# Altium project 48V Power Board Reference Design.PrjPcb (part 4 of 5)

## Sheet Power.SchDoc
size 431 x 279 mm; Date: Not shown in title block; ApprovedBy: Not shown in title block; CheckedBy: Not shown in title block; Author: Not shown in title block; CompanyName: Not shown in title block; Engineer: Not shown in title block; Organization: Not shown in title block; Address1: Not shown in title block; Address2: Not shown in title block; Address3: Not shown in title block; Address4: Not shown in title block; DocumentNumber: 5; Revision: Use project parameter SCH_Rev; SheetNumber: 14; SheetTotal: 15; PageSetup: Record=PageOptions¦CenterHorizontal=True¦CenterVertical=True¦PrintScale=1.00¦XCorrection=1.00¦YCorrection=1.00¦PrintKind=0¦BorderSize=5000000¦LeftOffset=0¦BottomOffset=0¦Orientation=2¦PaperLength=1000¦PaperWidth=1000¦Scale=100¦PaperSource=15¦PrintQuality=600¦MediaType=1¦DitherType=10¦PaperKind=Letter¦PrintScaleMode=1
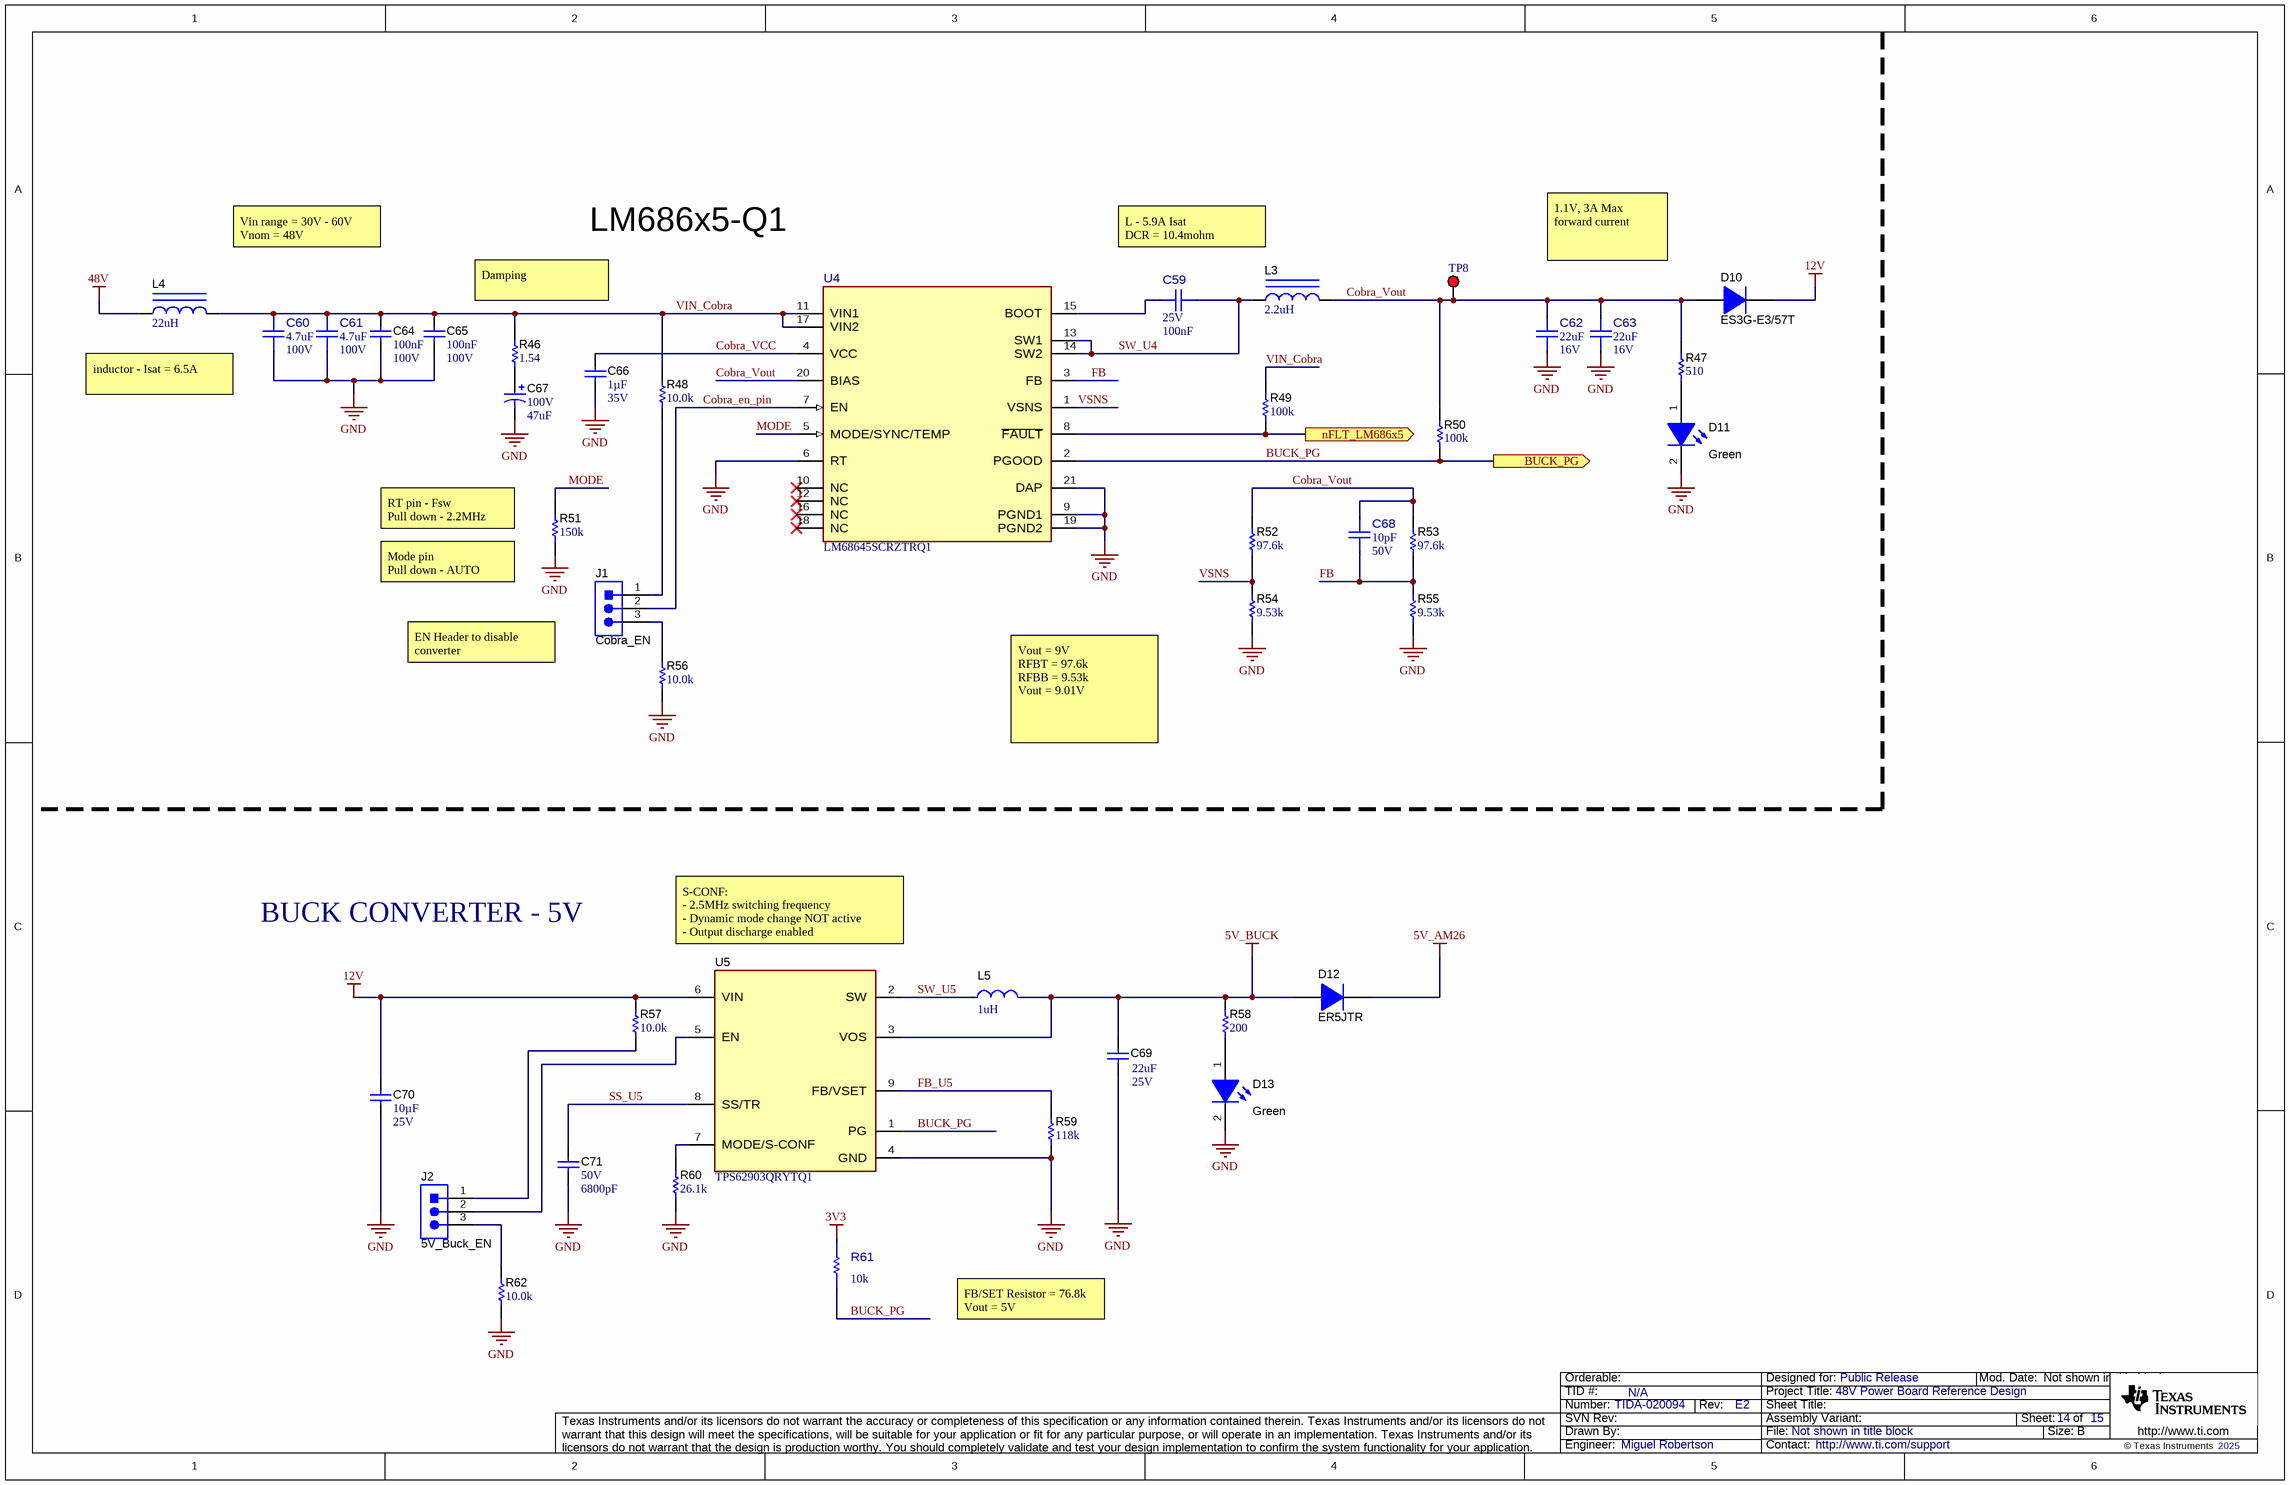
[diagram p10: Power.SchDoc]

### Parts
C59  VDC_V: 25V  Cap_F: 100nF  [FP-GCJ188R71E104KA12D_0603-MFG]  (hidden comment: GCJ188R71E104KA12D)
C60  ValueDisplayed: 4.7uF  VDC_V: 100V  [FP-GCJ32DC72A475KE01L_1210-MFG]  (hidden comment: GCJ32DC72A475KE01L)
C61  ValueDisplayed: 4.7uF  VDC_V: 100V  [FP-GCJ32DC72A475KE01L_1210-MFG]  (hidden comment: GCJ32DC72A475KE01L)
C62  ValueDisplayed: 22uF  VDC_V: 16V  [FP-EMK316BB7226ML-T_1206-MFG]  (hidden comment: EMK316BB7226ML-T)
C63  ValueDisplayed: 22uF  VDC_V: 16V  [FP-EMK316BB7226ML-T_1206-MFG]  (hidden comment: EMK316BB7226ML-T)
C64  Cap_F: 100nF  VDC_V: 100V  [0603]  (hidden comment: HMK107B7104KAHT)
C65  Cap_F: 100nF  VDC_V: 100V  [0603]  (hidden comment: HMK107B7104KAHT)
C66  Cap_F: 1µF  VDC_V: 35V  [0603]  (hidden comment: CGA3E1X7R1V105K080AE)
C67  VDC_V: 100V  ValueDisplayed: 47uF  [SM_RADIAL_H13]  (hidden comment: EEV-FK2A470Q)
C68  ValueDisplayed: 10pF  VDC_V: 50V  [FP-C0402C100K5RAC7867_0402-MFG]  (hidden comment: C0402C100K5RAC7867)
C69  VDC_V: 25V  ValueDisplayed: 22uF  [0805_HV]  (hidden comment: GRM21BR61E226ME44L)
C70  Cap_F: 10µF  VDC_V: 25V  [0805_HV]  (hidden comment: GRM21BZ71E106KE15L)
C71  VDC_V: 50V  ValueDisplayed: 6800pF  [0402]  (hidden comment: GRM155R71H682KA88D)
D10  ES3G-E3/57T  [SMC]
D11  value Green  [LTST-C191_Green]  (hidden comment: LTST-C191KGKT)
D12  ER5JTR  [SMC]
D13  value Green  [LTST-C191_Green]  (hidden comment: LTST-C191KGKT)
J1  Cobra_EN  [TSW-103-07-G-S]
J2  5V_Buck_EN  [TSW-103-07-G-S]
L3  ValueDisplayed: 2.2uH  [WE-TPC-XLH2]  (hidden comment: 7440650022)
L4  ValueDisplayed: 22uH  [WE-PD_1210]  (hidden comment: 7447709220)
L5  value 1uH  [FP-XGL4030-102MEC_SMD_IND_4MM0_4MM0-MFG]  (hidden comment: XGL4030-102MEC)
R46  ValueDisplayed: 1.54  [0603]  (hidden comment: CRCW06031R54FKEA)
R47  ValueDisplayed: 510  [0603]  (hidden comment: RC0603FR-07510RL)
R48  ValueDisplayed: 10.0k  [0603]  (hidden comment: ERJ-3EKF1002V)
R49  ValueDisplayed: 100k  [0603]  (hidden comment: RT0603BRD07100KL)
R50  ValueDisplayed: 100k  [0603]  (hidden comment: RT0603BRD07100KL)
R51  ValueDisplayed: 150k  [0603]  (hidden comment: ERJ-3EKF1002V)
R52  ValueDisplayed: 97.6k  [0603]  (hidden comment: RC0603FR-0797K6L)
R53  ValueDisplayed: 97.6k  [0603]  (hidden comment: RC0603FR-0797K6L)
R54  ValueDisplayed: 9.53k  [0603]  (hidden comment: RC0603FR-079K53L)
R55  ValueDisplayed: 9.53k  [0603]  (hidden comment: RC0603FR-079K53L)
R56  ValueDisplayed: 10.0k  [0603]  (hidden comment: ERJ-3EKF1002V)
R57  ValueDisplayed: 10.0k  [0603]  (hidden comment: ERJ-3EKF1002V)
R58  ValueDisplayed: 200  [0603]  (hidden comment: RC0603FR-07200RL)
R59  ValueDisplayed: 118k  [0603]  (hidden comment: CRCW0603118KFKEA)
R60  ValueDisplayed: 26.1k  [0603]  (hidden comment: RC0603FR-0726K1L)
R61  value 10k  [FP-RC0402JR-0710KL_0402-MFG]  (hidden comment: RC0402JR-0710KL)
R62  ValueDisplayed: 10.0k  [0603]  (hidden comment: ERJ-3EKF1002V)
TP8  COBRA_VOUT  [Keystone5010]  (value not drawn)
U4  LM68645SCRZTRQ1  [RZT0020A-MFG]
U5  TPS62903QRYTQ1  [RYT0009A-MFG]

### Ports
BUCK_PG (out), nFLT_LM686x5 (out)

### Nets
3V3: R61.2
5V_AM26: D12.1(K)
5V_BUCK: C69.1 D12.2(A) L5.2 R58.2 U5.3(VOS)
12V: C70.1 D10.1(K) R57.2 U5.6(VIN)
48V: L4.1
GND: C60.1 C61.1 C62.1 C63.1 C64.2 C65.2 C66.2 C67.2(-) C69.2 C70.2 C71.2 D11.2(K) D13.2(K) R51.1 R54.1 R55.1 R56.1 R59.1 R60.1 R62.1 U4.6(RT) U4.9(PGND1) U4.19(PGND2) U4.21(DAP) U5.4(GND)
BUCK_PG: R50.1 R61.1 U4.2(PGOOD) U5.1(PG) ; port BUCK_PG
Cobra_en_pin: J1.2 U4.7(EN)  [project net Cobra_en_pin_14]
Cobra_VCC: C66.1 U4.4(VCC)  [project net Cobra_VCC_14]
Cobra_Vout: C62.2 C63.2 C68.2 D10.2(A) L3.2 R47.2 R50.2 R52.2 R53.2 TP8.1 U4.20(BIAS)  [project net Cobra_Vout_14]
FB: C68.1 R53.1 R55.2 U4.3(FB)  [project net FB_14]
FB_U5: R59.2 U5.9(FB/VSET)  [project net FB_U5_14]
MODE: R51.2 U4.5(MODE/SYNC/TEMP)  [project net MODE_14]
nFLT_LM686x5: R49.1 U4.8(~{FAULT}) ; port nFLT_LM686x5
SS_U5: C71.1 U5.8(SS/TR)  [project net SS_U5_14]
SW_U4: C59.1 L3.1 U4.13(SW1) U4.14(SW2)  [project net SW_U4_14]
SW_U5: L5.1 U5.2(SW)  [project net SW_U5_14]
VIN_Cobra: C60.2 C61.2 C64.1 C65.1 L4.2 R46.2 R48.2 R49.2 U4.11(VIN1) U4.17(VIN2)  [project net VIN_Cobra_14]
VSNS: R52.1 R54.2 U4.1(VSNS)  [project net VSNS_14]
NetC59_2: C59.2 U4.15(BOOT)
NetC67_1: C67.1(+) R46.1
NetD11_1: D11.1(A) R47.1
NetD13_1: D13.1(A) R58.1
NetJ1_1: J1.1 R48.1
NetJ1_3: J1.3 R56.2
NetJ2_1: J2.1 R57.1
NetJ2_2: J2.2 U5.5(EN)
NetJ2_3: J2.3 R62.2
NetR60_2: R60.2 U5.7(MODE/S-CONF)

Not connected (* = marked no-connect by the designer): U4 10(NC)* 12(NC)* 16(NC)* 18(NC)*

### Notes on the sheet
- LM686x5-Q1
- Vin range = 30V - 60V                        Vnom = 48V
- Damping
- L - 5.9A Isat
  DCR = 10.4mohm
- 1.1V, 3A Max forward current
- inductor - Isat = 6.5A
- (near R51) RT pin - Fsw                          Pull down - 2.2MHz
- (near R51) Mode pin                           Pull down - AUTO
- EN Header to disable converter
- Vout = 9V
  RFBT = 97.6k
  RFBB = 9.53k
  Vout = 9.01V
- BUCK CONVERTER - 5V
- S-CONF:
  - 2.5MHz switching frequency
  - Dynamic mode change NOT active
  - Output discharge enabled
- FB/SET Resistor = 76.8k
  Vout = 5V

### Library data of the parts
C59 = CMP-0095670-2: Cap Ceramic 0.1uF 25V X7R 10% Pad SMD 0603 Soft Termination +125°C Automotive T/R; Manufacturer: Murata; Value: 100nF; AEC Qualified: Yes; AEC Grade: Grade 1; SizeZ_mm: 0.9mm; TempCo: 15%
C60 C61 = CMP-0093675-1: 4.7uF ±10% 100V Ceramic Capacitor X7S 1210 (3225 Metric); Manufacturer: Murata; Value: 4.7µF; AEC Qualified: Yes; TempCo: 22%; SizeZ_mm: 2.3mm; AEC Grade: Grade 1
C62 C63 = CMP-0123888-1: Ceramic Capacitor, 1206, 22uF, 20%, X7R, 15%, 16V; Manufacturer: Taiyo Yuden; AEC Qualified: No; Cap_F: 22µF; SizeZ_mm: 1.9mm; Value: 22µF
C64 C65 = CMP-0081011-1: CAP, CERM, 0.1 µF, 100 V,+/- 10%, X7R, AEC-Q200 Grade 1, 0603; Manufacturer: Taiyo Yuden; SizeAreaWB_mm2: 4.68; SizeArea_mm2: 1.28; AEC Qualified: Y; AEC Category: Q200; Value: 0.1uF; TaMax_C: 125°C; SizeZ_mm: 1; Polarized: N; TaMin_C: -55°C; SizeY_mm: 0.8; U/M: EA; SizeX_mm: 1.6; ValueDisplayed: 0.1µF
C66 = CMP-0081259-1: CAP, CERM, 1 µF, 35 V,+/- 10%, X7R, AEC-Q200 Grade 1, 0603; Manufacturer: TDK; SizeAreaWB_mm2: 4.68; SizeArea_mm2: 1.28; AEC Qualified: Y; AEC Category: Q200; Value: 1uF; TaMax_C: 125°C; SizeZ_mm: 1; Polarized: N; TaMin_C: -55°C; SizeY_mm: 0.8; U/M: EA; SizeX_mm: 1.6
C67 = CMP-0011225-2: CAP, AL, 47 uF, 100 V, +/- 20%, 0.32 ohm, AEC-Q200 Grade 2, SMD; Manufacturer: Panasonic; TaMin_C: -55°C; ESR_ohm: 0.32; Polarized: Y; SizeAreaWB_mm2: 263.5; U/M: EA; Value: 47uF; TaMax_C: 105°C; SizeZ_mm: 13.5; SizeX_mm: 15; Cap_Case: H13; SizeArea_mm2: 202.5; CompType: Capacitor; Cap_F: 47µF; IRMS_A: 500mA; AEC Grade: 2; AEC Category: Q200
C68 = CMP-0122034-1: 10 pF ±10% 50V Ceramic Capacitor X7R 0402 (1005 Metric); Manufacturer: KEMET; AEC Qualified: No; SizeZ_mm: 0.55mm; TempCo: 15%; Value: 10pF
C69 = CMP-0008305-2: CAP, CERM, 22 uF, 25 V, +/- 20%, X5R, 0805; Manufacturer: MuRata; TaMin_C: -55°C; Polarized: N; SizeAreaWB_mm2: 6.75; Value1: Unknown; U/M: EA; Value: 22uF; TaMax_C: 85°C; SizeZ_mm: 1.45; SizeX_mm: 2; SizeY_mm: 1.25; Cap_Case: 0805; SizeArea_mm2: 2.5; Cap_F: 22µF; AEC Category: Q200
C70 = CMP-0008378-2: CAP, CERM, 10 uF, 25 V, +/- 10%, X7R, 0805; Manufacturer: MuRata; TaMin_C: -55°C; Polarized: N; SizeAreaWB_mm2: 6.75; Value1: Unknown; U/M: EA; Value: 10uF; TaMax_C: 125°C; SizeZ_mm: 1.45; SizeX_mm: 2; SizeY_mm: 1.25; Cap_Case: 0805; SizeArea_mm2: 2.5; AEC Category: Q200
C71 = CMP-0006696-2: CAP, CERM, 6800 pF, 50 V, +/- 10%, X7R, 0402; Manufacturer: MuRata; TaMin_C: -55°C; Polarized: N; SizeAreaWB_mm2: 3; Value1: Unknown; U/M: EA; Value: 6800pF; TaMax_C: 125°C; SizeZ_mm: 0.6; SizeX_mm: 1; SizeY_mm: 0.5; Cap_F: 6.8nF; AEC Category: Q200
D10 = CMP-0077028-2: Diode, Ultrafast, 400 V, 3 A, SMC; Manufacturer: Vishay-Semiconductor; Green_Lifecycle: Not Set; SizeAreaWB_mm2: 83.2686; Vr_V: 400V; SizeY_mm: 6.22; Value1: 3A; TJmax_C: 150°C; SizeZ_mm: 2.6; Green_REACh: Incomplete; Vf_V: 1.1V; SizeArea_mm2: 50.5686; SizeX_mm: 8.13; Value: 400V; AEC Category: Q101
D11 D13 = CMP-0078478-1: LED, Green, SMD; Manufacturer: Lite-On; Io_A: 30mA; Power_TotalModule: 75mW; Green_Lifecycle: Not Set; Vr_V: 5V; Tjmax_C: 85°C; Green_REACh: Incomplete; Value1: 0.075W; Angle: 130; Ir_A: 10µA; Vf_V: 2V; Type: AlInGaP
D12 = CMP-0067546-2: Diode, Superfast Rectifier, 600 V, 5 A, SMC; Manufacturer: SMC Diode Solutions; Vr_V: 600V; TJmax_C: 150°C; Io_A: 5A; Value: 600V; SizeX_mm: 8.13; AEC Category: Q101; Vf_V: 1.7V; SizeY_mm: 6.22; SizeAreaWB_mm2: 83.2686; RJC_CperW: 47.0; SizeZ_mm: 2.6; SizeArea_mm2: 50.5686; AEC Qualified: N
J1 J2 = CMP-0075407-2: Header, 100mil, 3x1, Gold, TH; Manufacturer: Samtec; Pitch_mm: 2.54; Cert_VDE: N; Gender: Male; Cert_CSA: Y; Voltage_V: 550V; Green_REACh: Passed; Current_A: 6.3A; Green_Lifecycle: Active; Row_Count: 1
L3 = CMP-0063847-1: Inductor, Shielded Drum Core, Ferrite, 2.2 uH, 5.9 A, 0.0104 ohm, SMD; Manufacturer: Wurth Elektronik; Isat: 5.9A @ 35% inductance drop; Irms: 6.2A @ 30C rise; Green_Lifecycle: Active; SizeAreaWB_mm2: 144; DCR_ohm: 10.4m; Green_REACh: Passed; Value: 2.2uH; Imax_A: 5.9A; SizeZ_mm: 2.8; SizeX_mm: 10; SizeArea_mm2: 100; Ind_H: 2.2µH; AEC Category: Q200
L4 = CMP-0064538-2: Inductor, Shielded Drum Core, Ferrite, 22 uH, 5.3 A, 0.0233 ohm, SMD; Manufacturer: Wurth Elektronik; Isat: 6.5A @ 10% inductance drop; Irms: 5.3A @ 40C rise; Green_Lifecycle: Active; SizeAreaWB_mm2: 196; DCR_ohm: 23.3m; Green_REACh: Passed; Value: 22uH; Imax_A: 5.3A; SizeZ_mm: 10; SizeX_mm: 12; SizeArea_mm2: 144; Ind_H: 22µH; AEC Category: Q200
L5 = CMP-0090842-1: Power Inductor, shielded, composite, 1uH 20% tol, DCR 7.2mOhms, SRF 65MHz, Isat 4.8A, Irms 13A, AEC-Q200; Manufacturer: Coilcraft; TaMin_C: -40°C; TaMax_C: +125°C; Test Frequency: 1MHz; DCR_ohm: 7.2m; AEC Grade: Grade 1; SizeZ_mm: 3.1mm; AEC Qualified: Yes; Shrouded: true; Ind_H: 1µH
R46 = CMP-0022188-4: RES, 1.54, 1%, 0.1 W, AEC-Q200 Grade 0, 0603; Manufacturer: Vishay-Dale; Power_W: 100mW; TempCo: 100 ppm/C; Value_Code: 1R54; Value: 1.54; EIA_Code: E96; SizeX_mm: 1.6; SizeY_mm: 0.8; SizeZ_mm: 1; Value2: 0.1W; SizeArea_mm2: 1.28; AEC Qualified: Y; VDC_V: 75V; AEC Category: Q200; AEC Grade: 0
R47 = CMP-0023163-5: RES, 510, 1%, 0.1 W, 0603; Manufacturer: Yageo; Power_W: 100mW; TempCo: 100 ppm/C; Value_Code: 510R; Value: 510; SizeX_mm: 1.6; SizeY_mm: 0.8; SizeZ_mm: 1; Value2: 0.1W; SizeArea_mm2: 1.28; AEC Qualified: N; VDC_V: 75V; AEC Category: Q200; SizeAreaWB_mm2: 4.68
R48 R51 R56 R57 R62 = CMP-0022684-3: RES, 10.0 k, 1%, 0.1 W, 0603; Manufacturer: Panasonic; Power_W: 100mW; TempCo: 100 ppm/C; Value_Code: 10k0; U/M: EA; Value: 10.0k; EIA_Code: E96; Res_ohm: 10k; SizeX_mm: 1.6; SizeY_mm: 0.8; SizeZ_mm: 1; Value2: 0.1W; SizeArea_mm2: 1.28; VDC_V: 75V; AEC Category: Q200
R49 R50 = CMP-0023630-1: RES, 100 k, 0.1%, 0.1 W, 0603; Manufacturer: Yageo America; Power_W: 100mW; TempCo: 25 ppm/C; U/M: EA; Value: 100k; EIA_Code: E192; SizeX_mm: 1.6; SizeY_mm: 0.8; SizeZ_mm: 1; Value2: 0.1W; SizeArea_mm2: 1.28; VDC_V: 75V; AEC Category: Q200
R52 R53 = CMP-0023330-5: RES, 97.6 k, 1%, 0.1 W, 0603; Manufacturer: Yageo; Power_W: 100mW; TempCo: 100 ppm/C; Value_Code: 97k6; Value: 97.6k; EIA_Code: E96; SizeX_mm: 1.6; SizeY_mm: 0.8; SizeZ_mm: 1; Value2: 0.1W; SizeArea_mm2: 1.28; AEC Qualified: N; VDC_V: 75V; AEC Category: Q200; SizeAreaWB_mm2: 4.68
R54 R55 = CMP-0023335-5: RES, 9.53 k, 1%, 0.1 W, 0603; Manufacturer: Yageo; Power_W: 100mW; TempCo: 100 ppm/C; Value_Code: 9k53; Value: 9.53k; EIA_Code: E96; SizeX_mm: 1.6; SizeY_mm: 0.8; SizeZ_mm: 1; Value2: 0.1W; SizeArea_mm2: 1.28; AEC Qualified: N; VDC_V: 75V; AEC Category: Q200; SizeAreaWB_mm2: 4.68
R58 = CMP-0022902-5: RES, 200, 1%, 0.1 W, 0603; Manufacturer: Yageo; Power_W: 100mW; TempCo: 100 ppm/C; Value_Code: 200R; Value: 200; EIA_Code: E96; SizeX_mm: 1.6; SizeY_mm: 0.8; SizeZ_mm: 1; Value2: 0.1W; SizeArea_mm2: 1.28; AEC Qualified: N; VDC_V: 75V; AEC Category: Q200; SizeAreaWB_mm2: 4.68
R59 = CMP-0022014-4: RES, 118 k, 1%, 0.1 W, AEC-Q200 Grade 0, 0603; Manufacturer: Vishay-Dale; Power_W: 100mW; TempCo: 100 ppm/C; Value: 118k; EIA_Code: E96; SizeX_mm: 1.6; SizeY_mm: 0.8; SizeZ_mm: 1; Value2: 0.1W; SizeArea_mm2: 1.28; AEC Qualified: Y; VDC_V: 75V; AEC Category: Q200; AEC Grade: 0
R60 = CMP-0022957-5: RES, 26.1 k, 1%, 0.1 W, 0603; Manufacturer: Yageo; Power_W: 100mW; TempCo: 100 ppm/C; Value_Code: 26k1; Value: 26.1k; EIA_Code: E96; SizeX_mm: 1.6; SizeY_mm: 0.8; SizeZ_mm: 1; Value2: 0.1W; SizeArea_mm2: 1.28; AEC Qualified: N; VDC_V: 75V; AEC Category: Q200; SizeAreaWB_mm2: 4.68
R61 = CMP-0094798-1: Res Thick Film 0402 10K Ohm 5% 0.063W(1/16W) ±100ppm/C Pad SMD T/R; Manufacturer: YAGEO; Power_W: 63mW; TempCo: 100ppm/°C; SizeZ_mm: 0.4mm; AEC Qualified: No; VDC_V: 50V; Category Cd01000Bfc2916C6: Single Components; Category 5C6A91606D4187Ad: Resistors; Category 7542B8484461Ae85: Passive Components
TP8 = CMP-0055147-2: Test Point, Multipurpose, Red, TH; Manufacturer: Keystone Electronics; CT: TRUE; ContactFinish: Silver; Green_Lifecycle: Active; CNHeader: FALSE; Green_REACh: Passed
U4 = CMP-0096221-1: 3.5V to 65V Synchronous Step-Down Voltage Regulator; Manufacturer: Texas Instruments; Switching Topology: Buck; Number Of Outputs: 1; AEC Qualified: Yes; Standoff Height: 0mm; Output Type: AdjustableProgrammable; SizeZ_mm: 0.7mm
U5 = CMP-0093448-1: 3-V to 18-V, High Efficiency and Low IQ Buck Converter in QFN HR  Package with 165C Junction temperature; Manufacturer: Texas Instruments; SizeZ_mm: 1.05mm; Min Supply Voltage: 3V; Output Type: AdjustableProgrammable; Switching Frequency: 1/2.5MHz; Max Supply Voltage: 18V; Output Voltage: 0.4-5.5V; Number Of Outputs: 1; TJmax_C: +165°C; Standoff Height: 0mm; Nominal Supply Current: 8mA; AEC Qualified: Yes; AEC Grade: Grade 1; Max Duty Cycle: 100%

## Sheet (SPI Expander) TXE8124-Q1.SchDoc
size 431 x 279 mm; Date: Not shown in title block; ApprovedBy: Not shown in title block; CheckedBy: Not shown in title block; Author: Not shown in title block; CompanyName: Not shown in title block; Engineer: Not shown in title block; Organization: Not shown in title block; Address1: Not shown in title block; Address2: Not shown in title block; Address3: Not shown in title block; Address4: Not shown in title block; DocumentNumber: 1; Revision: Use project parameter SCH_Rev; SheetNumber: 13; SheetTotal: 15; PageSetup: Record=PageOptions¦CenterHorizontal=True¦CenterVertical=True¦PrintScale=1.00¦XCorrection=1.00¦YCorrection=1.00¦PrintKind=0¦BorderSize=5000000¦LeftOffset=0¦BottomOffset=0¦Orientation=2¦PaperLength=1000¦PaperWidth=1000¦Scale=100¦PaperSource=15¦PrintQuality=600¦MediaType=1¦DitherType=10¦PaperKind=Letter¦PrintScaleMode=1
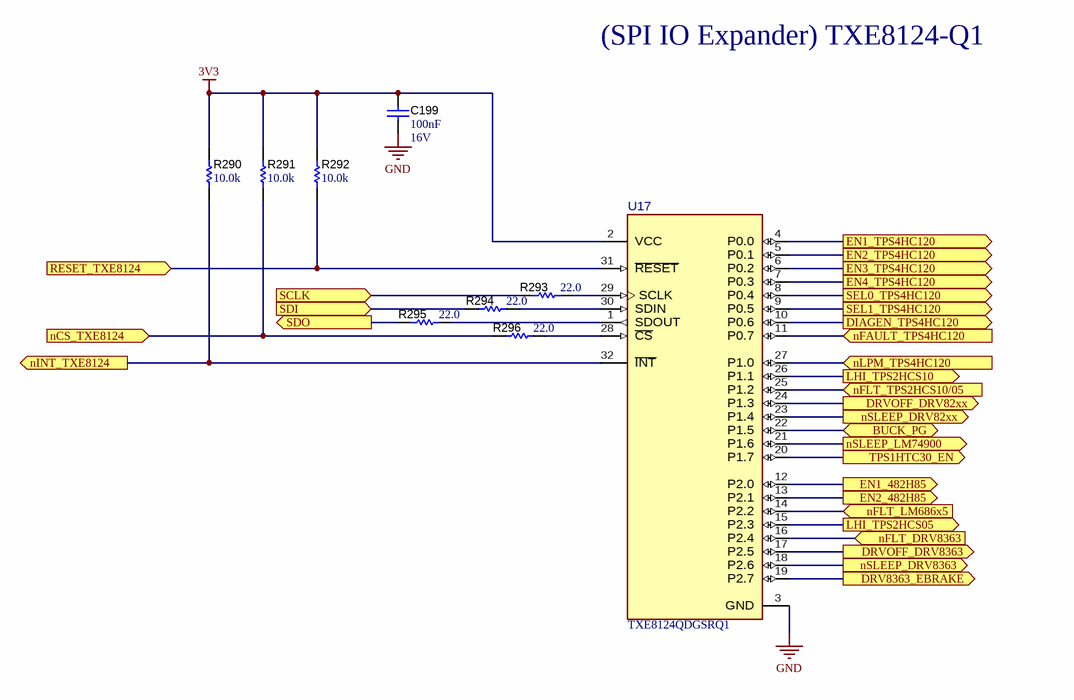
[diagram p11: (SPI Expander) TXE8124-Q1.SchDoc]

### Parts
C199  Cap_F: 100nF  VDC_V: 16V  [0603]  (hidden comment: GCM188R71C104KA37J)
R290  ValueDisplayed: 10.0k  [0603]  (hidden comment: ERJ-3EKF1002V)
R291  ValueDisplayed: 10.0k  [0603]  (hidden comment: ERJ-3EKF1002V)
R292  ValueDisplayed: 10.0k  [0603]  (hidden comment: ERJ-3EKF1002V)
R293  ValueDisplayed: 22.0  [0201]  (hidden comment: RC0201FR-0722RL)
R294  ValueDisplayed: 22.0  [0201]  (hidden comment: RC0201FR-0722RL)
R295  ValueDisplayed: 22.0  [0201]  (hidden comment: RC0201FR-0722RL)
R296  ValueDisplayed: 22.0  [0201]  (hidden comment: RC0201FR-0722RL)
U17  TXE8124QDGSRQ1  [DGS0032A-MFG]

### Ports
BUCK_PG (bidir), DIAGEN_TPS4HC120 (out), DRV8363_EBRAKE (out), DRVOFF_DRV82xx (out), DRVOFF_DRV8363 (out), EN1_482H85 (out), EN1_TPS4HC120 (out), EN2_482H85 (out), EN2_TPS4HC120 (out), EN3_TPS4HC120 (out), EN4_TPS4HC120 (out), LHI_TPS2HCS05 (out), LHI_TPS2HCS10 (out), nCS_TXE8124 (in), nFAULT_TPS4HC120 (in), nFLT_DRV8363 (in), nFLT_LM686x5 (in), nFLT_TPS2HCS10/05 (in), nINT_TXE8124 (out), nLPM_TPS4HC120 (in), nSLEEP_DRV82xx (out), nSLEEP_DRV8363 (out), nSLEEP_LM74900 (out), RESET_TXE8124 (in), SCLK (in), SDI (in), SDO (out), SEL0_TPS4HC120 (out), SEL1_TPS4HC120 (out), TPS1HTC30_EN (out)

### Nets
3V3: C199.1 R290.1 R291.1 R292.1 U17.2(VCC)
GND: C199.2 U17.3(GND)
: R294.1 ; port SDI
BUCK_PG: U17.22(P1.5) ; port BUCK_PG
DIAGEN_TPS4HC120: U17.10(P0.6) ; port DIAGEN_TPS4HC120
DRV8363_EBRAKE: U17.19(P2.7) ; port DRV8363_EBRAKE
DRVOFF_DRV82xx: U17.24(P1.3) ; port DRVOFF_DRV82xx
DRVOFF_DRV8363: U17.17(P2.5) ; port DRVOFF_DRV8363
EN1_482H85: U17.12(P2.0) ; port EN1_482H85
EN1_TPS4HC120: U17.4(P0.0) ; port EN1_TPS4HC120
EN2_482H85: U17.13(P2.1) ; port EN2_482H85
EN2_TPS4HC120: U17.5(P0.1) ; port EN2_TPS4HC120
EN3_TPS4HC120: U17.6(P0.2) ; port EN3_TPS4HC120
EN4_TPS4HC120: U17.7(P0.3) ; port EN4_TPS4HC120
LHI_TPS2HCS05: U17.15(P2.3) ; port LHI_TPS2HCS05
LHI_TPS2HCS10: U17.26(P1.1) ; port LHI_TPS2HCS10
nCS_TXE8124: R291.2 R296.1 ; port nCS_TXE8124
nFAULT_DRV8363: U17.16(P2.4) ; port nFLT_DRV8363
nFAULT_TPS4HC120: U17.11(P0.7) ; port nFAULT_TPS4HC120
nFLT_LM686x5: U17.14(P2.2) ; port nFLT_LM686x5
nFLT_TPS2HCS10/05: U17.25(P1.2) ; port nFLT_TPS2HCS10/05
nINT_TXE8124: R290.2 U17.32(~{INT}) ; port nINT_TXE8124
nLPM_TPS4HC120: U17.27(P1.0) ; port nLPM_TPS4HC120
nSLEEP_DRV82xx: U17.23(P1.4) ; port nSLEEP_DRV82xx
nSLEEP_DRV8363: U17.18(P2.6) ; port nSLEEP_DRV8363
nSLEEP_LM74900: U17.21(P1.6) ; port nSLEEP_LM74900
RESET_TXE8124: R292.2 U17.31(~{RESET}) ; port RESET_TXE8124
SCLK: R293.1 ; port SCLK
SDO: R295.1 ; port SDO
SEL0_TPS4HC120: U17.8(P0.4) ; port SEL0_TPS4HC120
SEL1_TPS4HC120: U17.9(P0.5) ; port SEL1_TPS4HC120
TPS1HTC30_EN: U17.20(P1.7) ; port TPS1HTC30_EN
NetR293_2: R293.2 U17.29(SCLK)
NetR294_2: R294.2 U17.30(SDIN)
NetR295_2: R295.2 U17.1(SDOUT)
NetR296_2: R296.2 U17.28(~{CS})

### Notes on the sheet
- (SPI IO Expander) TXE8124-Q1

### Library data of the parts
C199 = CMP-0007135-2: CAP, CERM, 0.1 uF, 16 V, +/- 10%, X7R, AEC-Q200 Grade 1, 0603; Manufacturer: MuRata; TaMin_C: -55°C; Polarized: N; SizeAreaWB_mm2: 4.68; Value1: Unknown; U/M: EA; Value: 0.1uF; TaMax_C: 125°C; SizeZ_mm: 1; SizeX_mm: 1.6; SizeY_mm: 0.8; SizeArea_mm2: 1.28; AEC Qualified: Y; AEC Category: Q200
R290-R292 = CMP-0022684-2: RES, 10.0 k, 1%, 0.1 W, 0603; Manufacturer: Panasonic; Power_W: 100mW; TempCo: 100 ppm/C; Value_Code: 10k0; U/M: EA; Value: 10.0k; EIA_Code: E96; Res_ohm: 10k; SizeX_mm: 1.6; SizeY_mm: 0.8; SizeZ_mm: 1; Value2: 0.1W; SizeArea_mm2: 1.28; VDC_V: 75V; AEC Category: Q200
R293-R296 = CMP-0027500-1: RES, 22.0, 1%, 0.05 W, 0201; Manufacturer: Yageo America; Power_W: 50mW; TempCo: 200 ppm/C; Value_Code: 22R0; U/M: EA; Value: 22.0; Res_ohm: 22; SizeX_mm: 0.6; SizeY_mm: 0.3; SizeZ_mm: 0.26; Value2: 0.05W; SizeArea_mm2: 0.18; AEC Qualified: N; VDC_V: 25V; AEC Category: Q200
U17 = CMP-0122953-2: Manufacturer: Texas Instruments; SizeZ_mm: 1.1mm; AEC Qualified: Yes; Standoff Height: 0.05mm; AEC Category: Q200; CompType: IC

## Sheet AM26 Connectors.SchDoc
size 431 x 279 mm; Date: Not shown in title block; ApprovedBy: Not shown in title block; CheckedBy: Not shown in title block; Author: Not shown in title block; CompanyName: Not shown in title block; Engineer: Not shown in title block; Organization: Not shown in title block; Address1: Not shown in title block; Address2: Not shown in title block; Address3: Not shown in title block; Address4: Not shown in title block; DocumentNumber: 14; Revision: Use project parameter SCH_Rev; SheetNumber: 12; SheetTotal: 15; PageSetup: Record=PageOptions¦CenterHorizontal=True¦CenterVertical=True¦PrintScale=1.00¦XCorrection=1.00¦YCorrection=1.00¦PrintKind=0¦BorderSize=5000000¦LeftOffset=0¦BottomOffset=0¦Orientation=2¦PaperLength=1000¦PaperWidth=1000¦Scale=100¦PaperSource=15¦PrintQuality=600¦MediaType=1¦DitherType=10¦PaperKind=Letter¦PrintScaleMode=1
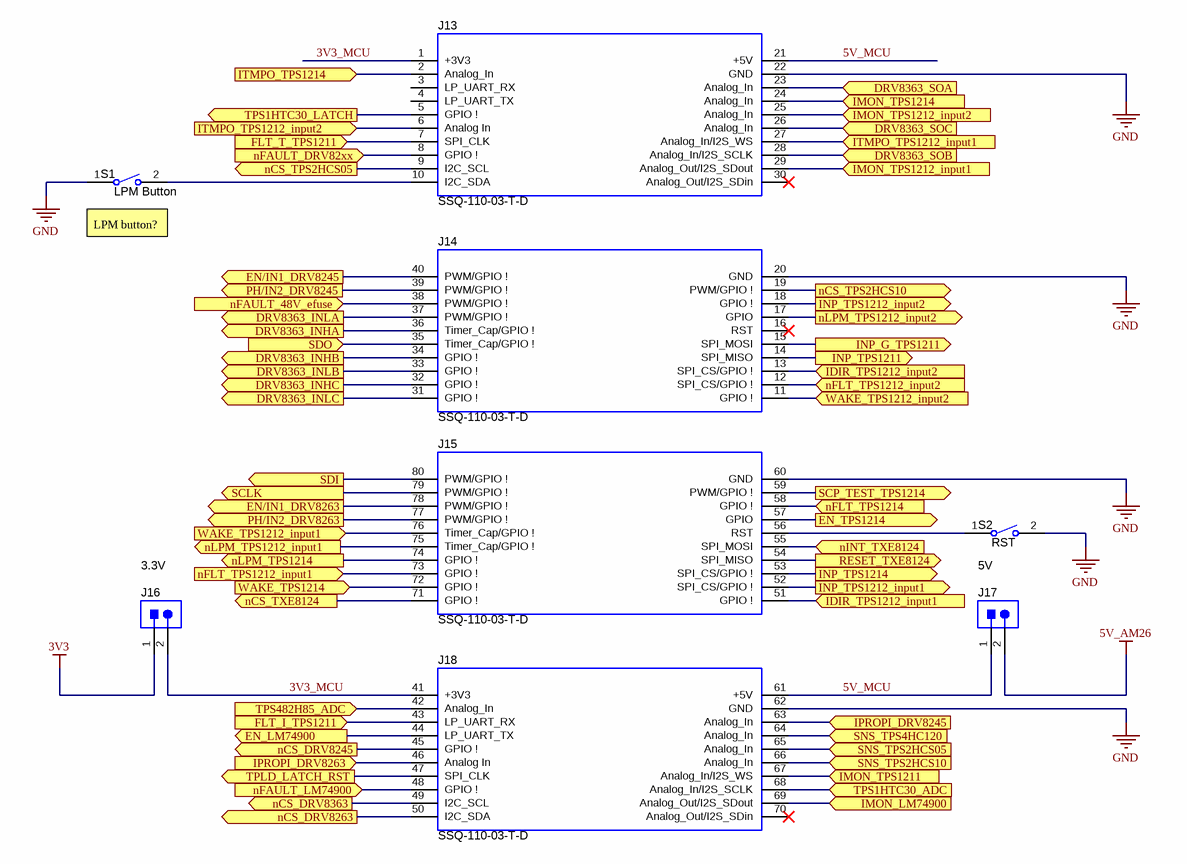
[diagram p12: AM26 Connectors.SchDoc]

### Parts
J13  SSQ-110-03-T-D  [BoosterPack_40pin_J1J3]
J14  SSQ-110-03-T-D  [BoosterPack_40pin_J2J4]
J15  SSQ-110-03-T-D  [BoosterPack_40pin_J6J8]
J16  3.3V  [Foxconn_HB3902U]
J17  5V  [Foxconn_HB3902U]
J18  SSQ-110-03-T-D  [BoosterPack_40pin_J5J7]
S1  LPM Button  [SW_147873-2]
S2  RST  [SW_147873-2]

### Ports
DRV8363_INHA (out), DRV8363_INHB (out), DRV8363_INHC (out), DRV8363_INLA (out), DRV8363_INLB (out), DRV8363_INLC (out), DRV8363_SOA (in), DRV8363_SOB (in), DRV8363_SOC (in), EN/IN1_DRV8245 (out), EN/IN1_DRV8263 (out), EN_LM74900 (out), EN_TPS1214 (out), FLT_I_TPS1211 (in), FLT_T_TPS1211 (in), IDIR_TPS1212_input1 (in), IDIR_TPS1212_input2 (in), IMON_LM74900 (in), IMON_TPS1211 (in), IMON_TPS1212_input1 (in), IMON_TPS1212_input2 (in), IMON_TPS1214 (in), INP_G_TPS1211 (out), INP_TPS1211 (out), INP_TPS1212_input1 (out), INP_TPS1212_input2 (out), INP_TPS1214 (out), IPROPI_DRV8245 (in), IPROPI_DRV8263 (in), ITMPO_TPS1212_input1 (in), ITMPO_TPS1212_input2 (in), ITMPO_TPS1214 (in), nCS_DRV8245 (out), nCS_DRV8263 (out), nCS_DRV8363 (out), nCS_TPS2HCS05 (out), nCS_TPS2HCS10 (out), nCS_TXE8124 (out), nFAULT_48V_efuse (in), nFAULT_DRV82xx (in), nFAULT_LM74900 (in), nFLT_TPS1212_input1 (in), nFLT_TPS1212_input2 (in), nFLT_TPS1214 (in), nINT_TXE8124 (in), nLPM_TPS1212_input1 (out), nLPM_TPS1212_input2 (out), nLPM_TPS1214 (out), PH/IN2_DRV8245 (out), PH/IN2_DRV8263 (out), RESET_TXE8124 (out), SCLK (out), SCP_TEST_TPS1214 (out), SDI (out), SDO (in), SNS_TPS2HCS05 (in), SNS_TPS2HCS10 (in), SNS_TPS4HC120 (in), TPLD_LATCH_RST (out), TPS1HTC30_ADC (in), TPS1HTC30_LATCH (out), TPS482H85_ADC (in), WAKE_TPS1212_input1 (in), WAKE_TPS1212_input2 (in), WAKE_TPS1214 (in)

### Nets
3V3: J16.1
5V_AM26: J17.2
GND: J13.22(GND) J14.20(GND) J15.60(GND) J18.62(GND) S1.1 S2.2
3V3_MCU: J13.1(+3V3) J16.2 J18.41(+3V3)  [project net 3V3_MCU_12]
5V_MCU: J13.21(+5V) J17.1 J18.61(+5V)  [project net 5V_MCU_12]
: J15.80(PWM/GPIO_!) ; port SDI
DRV8363_INHA: J14.36(Timer_Cap/GPIO_!) ; port DRV8363_INHA
DRV8363_INHB: J14.34(GPIO_!) ; port DRV8363_INHB
DRV8363_INHC: J14.32(GPIO_!) ; port DRV8363_INHC
DRV8363_INLA: J14.37(PWM/GPIO_!) ; port DRV8363_INLA
DRV8363_INLB: J14.33(GPIO_!) ; port DRV8363_INLB
DRV8363_INLC: J14.31(GPIO_!) ; port DRV8363_INLC
DRV8363_SOA: J13.23(Analog_In) ; port DRV8363_SOA
DRV8363_SOB: J13.28(Analog_In/I2S_SCLK) ; port DRV8363_SOB
DRV8363_SOC: J13.26(Analog_In) ; port DRV8363_SOC
EN/IN1_DRV8245: J14.40(PWM/GPIO_!) ; port EN/IN1_DRV8245
EN/IN1_DRV8263: J15.78(PWM/GPIO_!) ; port EN/IN1_DRV8263
EN_LM74900: J18.44(LP_UART_TX) ; port EN_LM74900
EN_TPS1214: J15.57(GPIO) ; port EN_TPS1214
FLT_I_TPS1211: J18.43(LP_UART_RX) ; port FLT_I_TPS1211
FLT_T_TPS1211: J13.7(SPI_CLK) ; port FLT_T_TPS1211
IDIR_TPS1212_input1: J15.51(GPIO_!) ; port IDIR_TPS1212_input1
IDIR_TPS1212_input2: J14.13(SPI_CS/GPIO_!) ; port IDIR_TPS1212_input2
IMON_LM74900: J18.69(Analog_Out/I2S_SDout) ; port IMON_LM74900
IMON_TPS1211: J18.67(Analog_In/I2S_WS) ; port IMON_TPS1211
IMON_TPS1212_input1: J13.29(Analog_Out/I2S_SDout) ; port IMON_TPS1212_input1
IMON_TPS1212_input2: J13.25(Analog_In) ; port IMON_TPS1212_input2
IMON_TPS1214: J13.24(Analog_In) ; port IMON_TPS1214
INP_G_TPS1211: J14.15(SPI_MOSI) ; port INP_G_TPS1211
INP_TPS1211: J14.14(SPI_MISO) ; port INP_TPS1211
INP_TPS1212_input1: J15.52(SPI_CS/GPIO_!) ; port INP_TPS1212_input1
INP_TPS1212_input2: J14.18(GPIO_!) ; port INP_TPS1212_input2
INP_TPS1214: J15.53(SPI_CS/GPIO_!) ; port INP_TPS1214
IPROPI_DRV8245: J18.63(Analog_In) ; port IPROPI_DRV8245
IPROPI_DRV8263: J18.46(Analog_In) ; port IPROPI_DRV8263
ITMPO_TPS1212_input1: J13.27(Analog_In/I2S_WS) ; port ITMPO_TPS1212_input1
ITMPO_TPS1212_input2: J13.6(Analog_In) ; port ITMPO_TPS1212_input2
ITMPO_TPS1214: J13.2(Analog_In) ; port ITMPO_TPS1214
nCS_DRV8245: J18.45(GPIO_!) ; port nCS_DRV8245
nCS_DRV8263: J18.50(I2C_SDA) ; port nCS_DRV8263
nCS_DRV8363: J18.49(I2C_SCL) ; port nCS_DRV8363
nCS_TPS2HCS05: J13.9(I2C_SCL) ; port nCS_TPS2HCS05
nCS_TPS2HCS10: J14.19(PWM/GPIO_!) ; port nCS_TPS2HCS10
nCS_TXE8124: J15.71(GPIO_!) ; port nCS_TXE8124
nFAULT_48V_efuse: J14.38(PWM/GPIO_!) ; port nFAULT_48V_efuse
nFAULT_1214: J15.58(GPIO_!) ; port nFLT_TPS1214
nFAULT_DRV82xx: J13.8(GPIO_!) ; port nFAULT_DRV82xx
nFAULT_LM74900: J18.48(GPIO_!) ; port nFAULT_LM74900
nFLT_TPS1212_input1: J15.73(GPIO_!) ; port nFLT_TPS1212_input1
nFLT_TPS1212_input2: J14.12(SPI_CS/GPIO_!) ; port nFLT_TPS1212_input2
nINT_TXE8124: J15.55(SPI_MOSI) ; port nINT_TXE8124
nLPM_TPS1212_input1: J15.75(Timer_Cap/GPIO_!) ; port nLPM_TPS1212_input1
nLPM_TPS1212_input2: J14.17(GPIO) ; port nLPM_TPS1212_input2
nLPM_TPS1214: J15.74(GPIO_!) ; port nLPM_TPS1214
PH/IN2_DRV8245: J14.39(PWM/GPIO_!) ; port PH/IN2_DRV8245
PH/IN2_DRV8263: J15.77(PWM/GPIO_!) ; port PH/IN2_DRV8263
RESET_TXE8124: J15.54(SPI_MISO) ; port RESET_TXE8124
SCLK: J15.79(PWM/GPIO_!) ; port SCLK
SCP_TEST_TPS1214: J15.59(PWM/GPIO_!) ; port SCP_TEST_TPS1214
SDO: J14.35(Timer_Cap/GPIO_!) ; port SDO
SNS_TPS2HCS05: J18.65(Analog_In) ; port SNS_TPS2HCS05
SNS_TPS2HCS10: J18.66(Analog_In) ; port SNS_TPS2HCS10
SNS_TPS4HC120: J18.64(Analog_In) ; port SNS_TPS4HC120
TPLD_LATCH_RST: J18.47(SPI_CLK) ; port TPLD_LATCH_RST
TPS1HTC30_ADC: J18.68(Analog_In/I2S_SCLK) ; port TPS1HTC30_ADC
TPS1HTC30_LATCH: J13.5(GPIO_!) ; port TPS1HTC30_LATCH
TPS482H85_ADC: J18.42(Analog_In) ; port TPS482H85_ADC
WAKE_TPS1212_input1: J15.76(Timer_Cap/GPIO_!) ; port WAKE_TPS1212_input1
WAKE_TPS1212_input2: J14.11(GPIO_!) ; port WAKE_TPS1212_input2
WAKE_TPS1214: J15.72(GPIO_!) ; port WAKE_TPS1214
NetJ13_10: J13.10(I2C_SDA) S1.2
NetJ15_56: J15.56(RST) S2.1

Not connected (* = marked no-connect by the designer): J13 3(LP_UART_RX) 4(LP_UART_TX) 30(Analog_Out/I2S_SDin)*; J14 16(RST)*; J18 70(Analog_Out/I2S_SDin)*

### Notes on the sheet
- (near S1) LPM button?

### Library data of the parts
J13 = CMP-0003837-2: Receptacle, 2.54mm, 10x2, Tin, TH; Alternate PartNumber: CRD-081413-A-G; Manufacturer: Samtec; Alternate Manufacturer: Major League Electronics; Note: Booster Pack 40 pin J1 and J3; Green_Lifecycle: Active; Green_REACh: Incomplete
J14 = CMP-0078266-2: Receptacle, 2.54mm, 10x2, Tin, TH; Alternate PartNumber: CRD-081413-A-G; Manufacturer: Samtec; Alternate Manufacturer: Major League Electronics; Note: Booster Pack 40 pin J2 and J4; Green_REACh: Incomplete; Green_Lifecycle: Active
J15 = CMP-0081071-3: Receptacle, 2.54mm, 10x2, Tin, TH; Alternate PartNumber: CRD-081413-A-G; Manufacturer: Samtec; Alternate Manufacturer: Major League Electronics; Note: Booster Pack 40 pin J6 and J8; Green_REACh: Incomplete; Green_Lifecycle: Active
J16 J17 = CMP-0075286-1: Header, 2.54mm, 2x1, Gold, TH; Manufacturer: Foxconn; PartNumber: HB3902U; CNHeader: True; Current_A: 3A; Shrouded: N; Gender: Male; Voltage_V: 500V; Row_Count: 1; Pitch_mm: 2.54; CT: False; Cert_UL: Y
J18 = CMP-0081070-3: Receptacle, 2.54mm, 10x2, Tin, TH; Alternate PartNumber: CRD-081413-A-G; Manufacturer: Samtec; Alternate Manufacturer: Major League Electronics; Note: Booster Pack 40 pin J5 and J7; Green_REACh: Incomplete; Green_Lifecycle: Active
S1 S2 = CMP-0002294-1: Switch, SPST, Off-On, 50 mA,24V, SMD; PartNumber: 147873-2; Manufacturer: TE Connectivity; CurrentRating_mA: 50A; PositionCount: 1; SizeX_mm: 6.8; SizeY_mm: 3.5; SizeZ_mm: 4.65; SizeArea_mm2: 23.8; SizeAreaWB_mm2: 48.4

## Sheet Backbone_input1.SchDoc
size 431 x 279 mm; Date: Not shown in title block; ApprovedBy: Not shown in title block; CheckedBy: Not shown in title block; Author: Not shown in title block; CompanyName: Not shown in title block; Engineer: Not shown in title block; Organization: Not shown in title block; Address1: Not shown in title block; Address2: Not shown in title block; Address3: Not shown in title block; Address4: Not shown in title block; DocumentNumber: 3; Revision: Use project parameter SCH_Rev; SheetNumber: 2; SheetTotal: 15; PageSetup: Record=PageOptions¦CenterHorizontal=True¦CenterVertical=True¦PrintScale=1.00¦XCorrection=1.00¦YCorrection=1.00¦PrintKind=0¦BorderSize=5000000¦LeftOffset=0¦BottomOffset=0¦Orientation=2¦PaperLength=1000¦PaperWidth=1000¦Scale=100¦PaperSource=15¦PrintQuality=600¦MediaType=1¦DitherType=10¦PaperKind=Letter¦PrintScaleMode=1
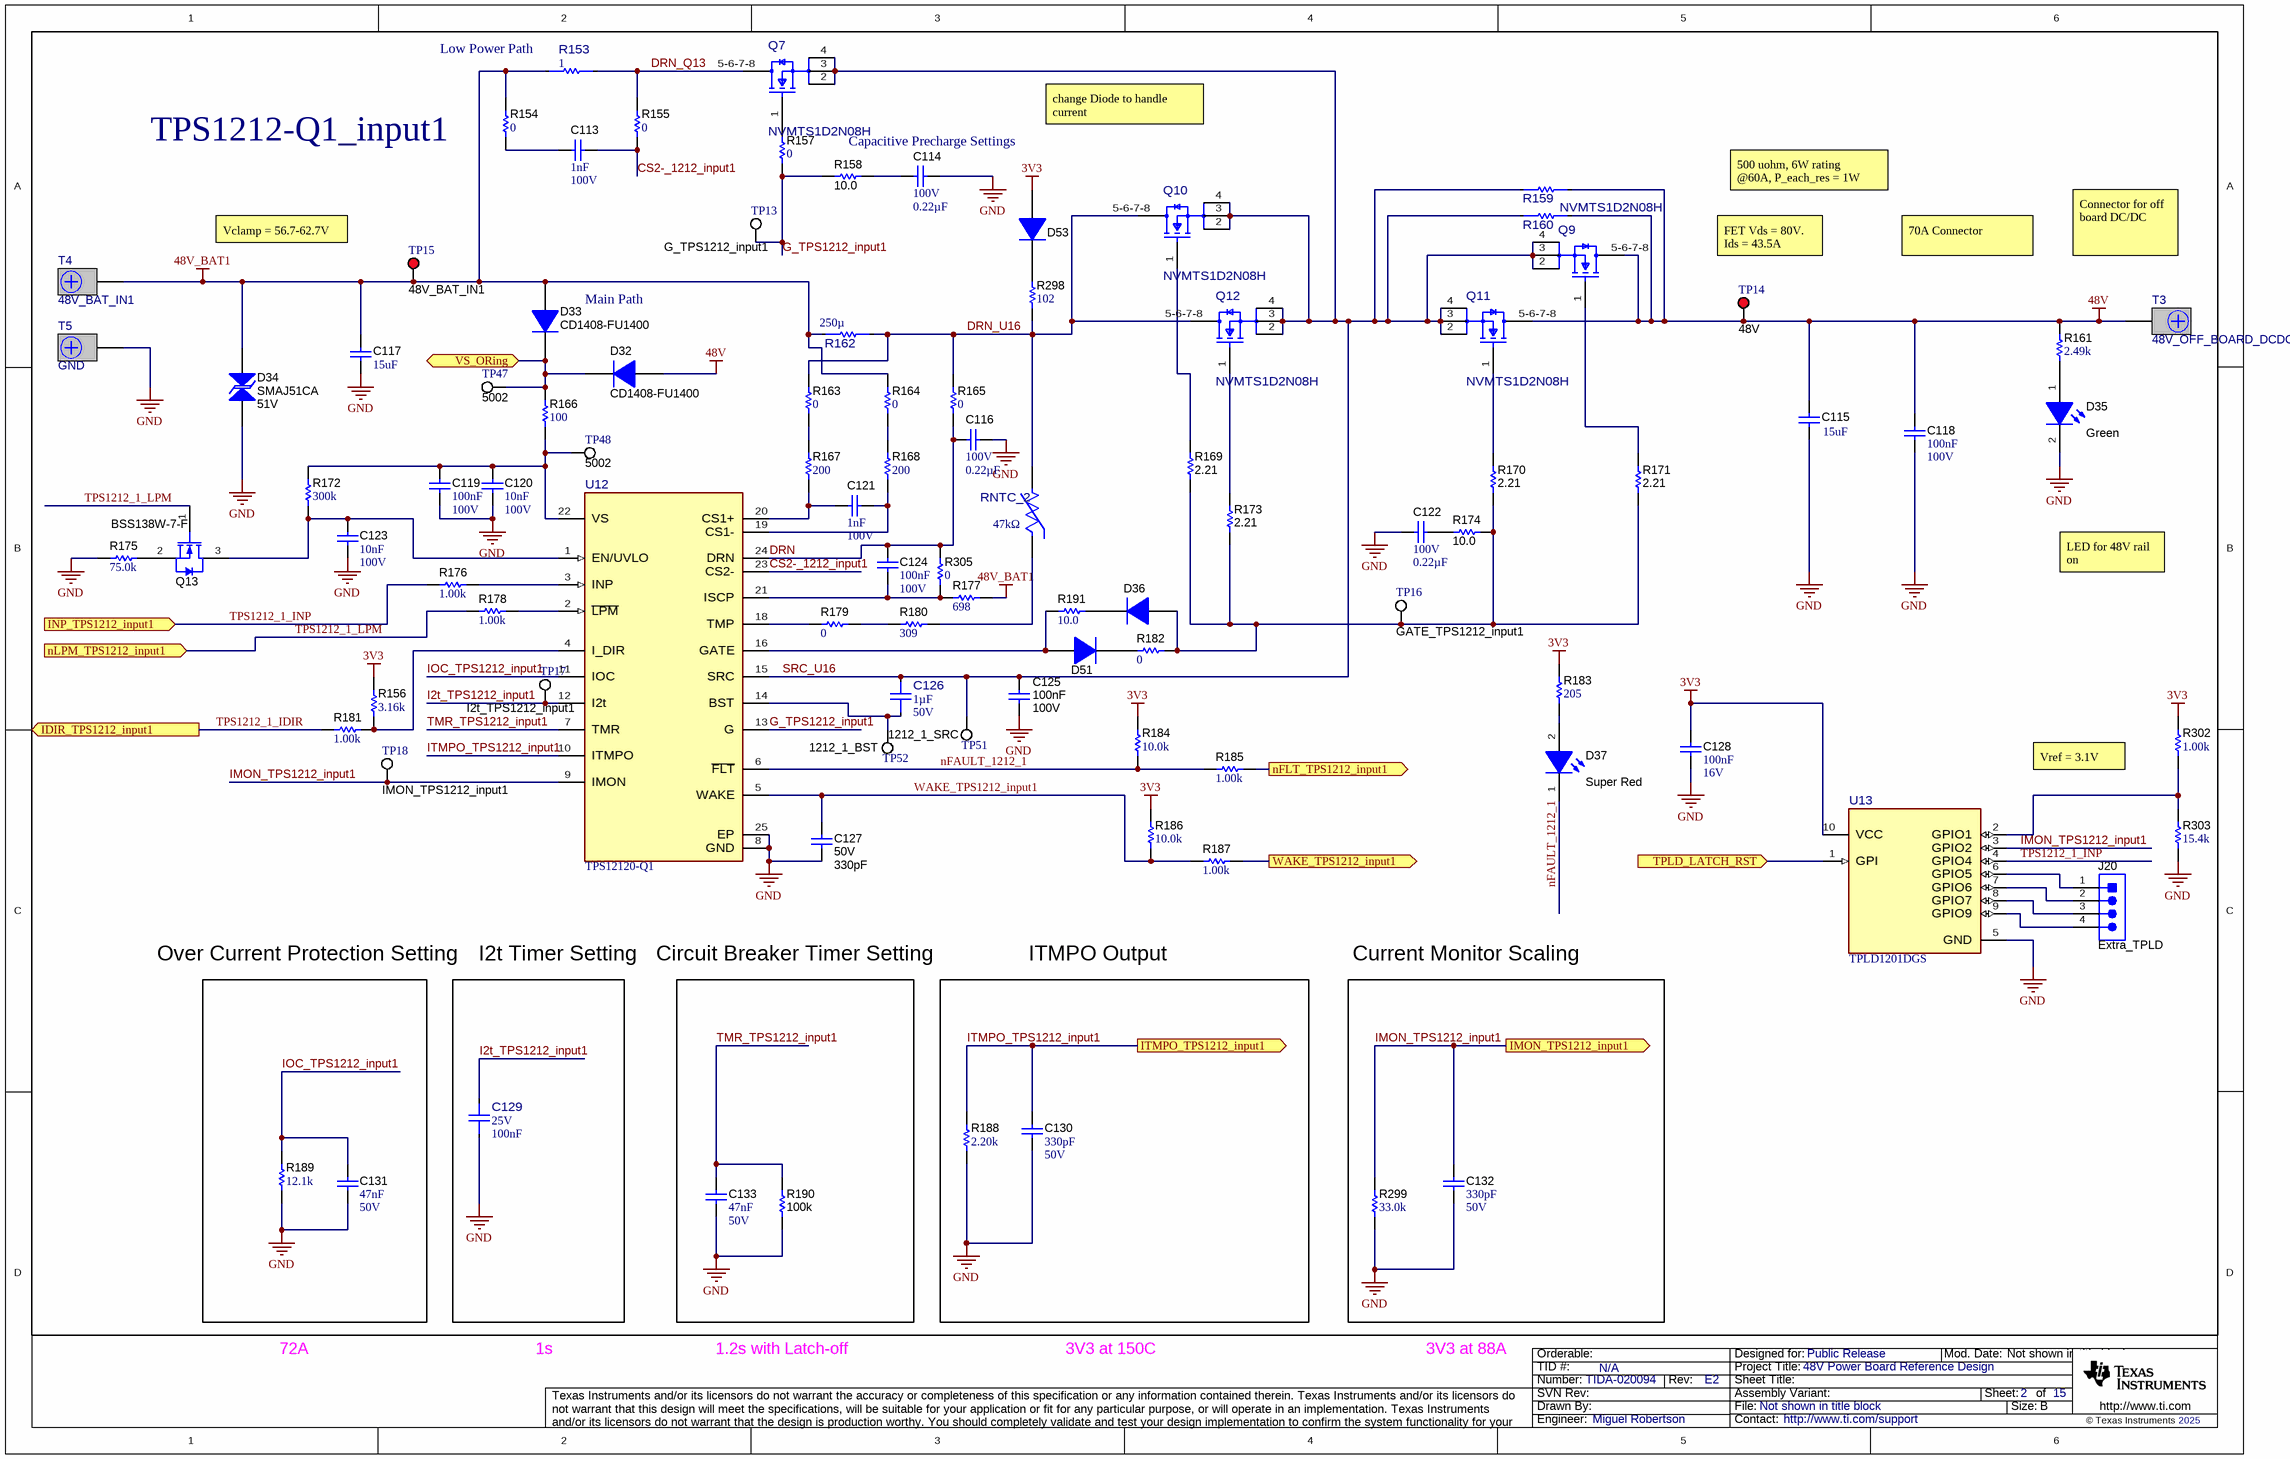
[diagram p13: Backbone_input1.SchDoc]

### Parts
C113  Cap_F: 1nF  VDC_V: 100V  [0603]  (hidden comment: CGA3E2X7R2A102K080AA)
C114  VDC_V: 100V  ValueDisplayed: 0.22µF  [0603]  (hidden comment: HMK107C7224MAHTE)
C115  ValueDisplayed: 15uF  [KCM55W]  (hidden comment: KCM55WR72A156MH01K)
C116  VDC_V: 100V  ValueDisplayed: 0.22µF  [0603]  (hidden comment: HMK107C7224MAHTE)
C117  ValueDisplayed: 15uF  [KCM55W]  (hidden comment: KCM55WR72A156MH01K)
C118  Cap_F: 100nF  VDC_V: 100V  [0603]  (hidden comment: HMK107B7104KAHT)
C119  Cap_F: 100nF  VDC_V: 100V  [0603]  (hidden comment: HMK107B7104KAHT)
C120  Cap_F: 10nF  VDC_V: 100V  [0603]  (hidden comment: CGA3E2X7R2A103K080AA)
C121  Cap_F: 1nF  VDC_V: 100V  [0603]  (hidden comment: CGA3E2X7R2A102K080AA)
C122  VDC_V: 100V  ValueDisplayed: 0.22µF  [0603]  (hidden comment: HMK107C7224MAHTE)
C123  Cap_F: 10nF  VDC_V: 100V  [0603]  (hidden comment: CGA3E2X7R2A103K080AA)
C124  Cap_F: 100nF  VDC_V: 100V  [0603]  (hidden comment: HMK107B7104KAHT)
C125  Cap_F: 100nF  VDC_V: 100V  [0805_HV]  (hidden comment: CGA4J2X7R2A104K125AA)
C126  Cap_F: 1µF  VDC_V: 50V  [FP-CL10B105KB9VPJC_0603-MFG]  (hidden comment: CL10B105KB9VPJC)
C127  VDC_V: 50V  ValueDisplayed: 330pF  [0402]  (hidden comment: GRM155R71H331KA01D)
C128  Cap_F: 100nF  VDC_V: 16V  [0603]  (hidden comment: GCM188R71C104KA37J)
C129  VDC_V: 25V  Cap_F: 100nF  [FP-GCJ188R71E104KA12D_0603-MFG]  (hidden comment: GCJ188R71E104KA12D)
C130  Cap_F: 330pF  VDC_V: 50V  [0603]  (hidden comment: C0603C331K5RACTU)
C131  Cap_F: 47nF  VDC_V: 50V  [0603]  (hidden comment: CGA3E2X7R1H473K080AA)
C132  Cap_F: 330pF  VDC_V: 50V  [0603]  (hidden comment: C0603C331K5RACTU)
C133  Cap_F: 47nF  VDC_V: 50V  [0603]  (hidden comment: CGA3E2X7R1H473K080AA)
D32  CD1408-FU1400  [Diode_1408]
D33  CD1408-FU1400  [Diode_1408]
D34  SMAJ51CA  value 51V  [SMA_Bi]
D35  value Green  [LTST-C191_Green]  (hidden comment: LTST-C191KGKT)
D36  1N4148W-TP  [SOD-123]  (value not drawn)
D37  value Super Red  [WL-SMCW_RED]  (hidden comment: 150060SS75000)
D51  1N4148W-TP  [SOD-123]  (value not drawn)
D53  1N4148W-TP  [SOD-123]  (value not drawn)
J20  Extra_TPLD  [TSW-104-07-G-S]
Q7  NVMTS1D2N08H  [FP-NVMTS1D2N08H_DFNW8-MFG]
Q9  NVMTS1D2N08H  [FP-NVMTS1D2N08H_DFNW8-MFG]
Q10  NVMTS1D2N08H  [FP-NVMTS1D2N08H_DFNW8-MFG]
Q11  NVMTS1D2N08H  [FP-NVMTS1D2N08H_DFNW8-MFG]
Q12  NVMTS1D2N08H  [FP-NVMTS1D2N08H_DFNW8-MFG]
Q13  BSS138W-7-F  [SOT-323]
R153  value 1  [FP-VMP-1R00-1.0-U_2010-MFG]  (hidden comment: VMP-1R00-1.0-U)
R154  ValueDisplayed: 0  [0603]  (hidden comment: CRCW06030000Z0EA)
R155  ValueDisplayed: 0  [0603]  (hidden comment: CRCW06030000Z0EA)
R156  ValueDisplayed: 3.16k  [0603]  (hidden comment: RC0603FR-073K16L)
R157  ValueDisplayed: 0  [0603]  (hidden comment: CRCW06030000Z0EA)
R158  ValueDisplayed: 10.0  [0805_HV]  (hidden comment: RC0805FR-0710RL)
R159  CSS2H-2512R-L500F  [FP-CSS2H-2512R-L500F_2512-MFG]  (value not drawn)
R160  CSS2H-2512R-L500F  [FP-CSS2H-2512R-L500F_2512-MFG]  (value not drawn)
R161  ValueDisplayed: 2.49k  [0603]  (hidden comment: RC0603FR-072K49L)
R162  value 250µ  [FP-HoLRS2512_2512-MFG]  (hidden comment: HoLRS2512-0.25mR-1%)
R163  ValueDisplayed: 0  [0603]  (hidden comment: CRCW06030000Z0EA)
R164  ValueDisplayed: 0  [0603]  (hidden comment: CRCW06030000Z0EA)
R165  ValueDisplayed: 0  [0603]  (hidden comment: CRCW06030000Z0EA)
R166  ValueDisplayed: 100  [0603]  (hidden comment: ERJ-3EKF1000V)
R167  ValueDisplayed: 200  [0603]  (hidden comment: RC0603FR-07200RL)
R168  ValueDisplayed: 200  [0603]  (hidden comment: RC0603FR-07200RL)
R169  ValueDisplayed: 2.21  [0603]  (hidden comment: RC0603FR-072R21L)
R170  ValueDisplayed: 2.21  [0603]  (hidden comment: RC0603FR-072R21L)
R171  ValueDisplayed: 2.21  [0603]  (hidden comment: RC0603FR-072R21L)
R172  ValueDisplayed: 300k  [0603]  (hidden comment: RC0603FR-07300KL)
R173  ValueDisplayed: 2.21  [0603]  (hidden comment: RC0603FR-072R21L)
R174  ValueDisplayed: 10.0  [0805_HV]  (hidden comment: RC0805FR-0710RL)
R175  ValueDisplayed: 75.0k  [0603]  (hidden comment: RC0603FR-0775KL)
R176  ValueDisplayed: 1.00k  [0603]  (hidden comment: RC0603FR-071KL)
R177  ValueDisplayed: 698  [0603]  (hidden comment: RC0603FR-07698RL)
R178  ValueDisplayed: 1.00k  [0603]  (hidden comment: RC0603FR-071KL)
R179  ValueDisplayed: 0  [0603]  (hidden comment: CRCW06030000Z0EA)
R180  ValueDisplayed: 309  [0603]  (hidden comment: RC0603FR-07309RL)
R181  ValueDisplayed: 1.00k  [0603]  (hidden comment: RC0603FR-071KL)
R182  ValueDisplayed: 0  [0603]  (hidden comment: CRCW06030000Z0EA)
R183  ValueDisplayed: 205  [0603]  (hidden comment: RC0603FR-07205RL)
R184  ValueDisplayed: 10.0k  [TNPW0603]  (hidden comment: TNPW060310K0BEEA)
R185  ValueDisplayed: 1.00k  [0603]  (hidden comment: RC0603FR-071KL)
R186  ValueDisplayed: 10.0k  [TNPW0603]  (hidden comment: TNPW060310K0BEEA)
R187  ValueDisplayed: 1.00k  [0603]  (hidden comment: RC0603FR-071KL)
R188  ValueDisplayed: 2.20k  [0603]  (hidden comment: RC0603FR-072K2L)
R189  ValueDisplayed: 12.1k  [0603]  (hidden comment: RC0603FR-0712K1L)
R190  ValueDisplayed: 100k  [0603]  (hidden comment: CRCW0603100KFKEA)
R191  ValueDisplayed: 10.0  [0603]  (hidden comment: RC0603FR-0710RL)
R298  ValueDisplayed: 102  [0603]  (hidden comment: RC0603FR-07102RL)
R299  ValueDisplayed: 33.0k  [0603]  (hidden comment: RC0603FR-0733KL)
R302  ValueDisplayed: 1.00k  [0603]  (hidden comment: RC0603FR-071KL)
R303  ValueDisplayed: 15.4k  [0603]  (hidden comment: RC0603FR-0715K4L)
R305  ValueDisplayed: 0  [0603]  (hidden comment: CRCW06030000Z0EA)
RNTC_2  value 47kΩ  [FP-NCU18WB473J6SRB_0603-MFG]  (hidden comment: NCU18WB473J6SRB)
T3  48V_OFF_BOARD_DCDC  [Panduit_CXS70-14-C]
T4  48V_BAT_IN1  [Panduit_CXS70-14-C]
T5  GND  [Panduit_CXS70-14-C]
TP13  G_TPS1212_input1  [Keystone5012]
TP14  48V  [Keystone5010]
TP15  48V_BAT_IN1  [Keystone5010]
TP16  GATE_TPS1212_input1  [Keystone5012]
TP17  I2t_TPS1212_input1  [Keystone5012]
TP18  IMON_TPS1212_input1  [Keystone5012]
TP47  5002  [Keystone5002]
TP48  5002  [Keystone5002]
TP51  1212_1_SRC  [Keystone5012]
TP52  1212_1_BST  [Keystone5012]
U12  TPS12120-Q1  [RGE0023A-MFG]
U13  TPLD1201DGS  [DGS0010A-MFG]

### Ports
IDIR_TPS1212_input1 (out), IMON_TPS1212_input1 (out), INP_TPS1212_input1 (in), ITMPO_TPS1212_input1 (out), nFLT_TPS1212_input1 (out), nLPM_TPS1212_input1 (in), TPLD_LATCH_RST (in), VS_ORing (bidir), WAKE_TPS1212_input1 (out)

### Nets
3V3: C128.1 D53.2(A) R156.2 R183.2 R184.2 R186.2 R302.2 U13.10(VCC)
48V: C115.1 C118.1 D32.2(A) Q9.5-6-7-8(D) Q11.5-6-7-8(D) R159.2 R160.2 R161.2 T3.1 TP14.1
48V_BAT1: C117.1 D33.2(A) D34.2 R153.1 R154.2 R162.1 R164.2 R177.2 T4.1 TP15.1
GND: C114.1 C115.2 C116.1 C117.2 C118.2 C119.2 C120.2 C122.2 C123.2 C125.2 C127.2 C128.2 C129.1 C130.2 C131.2 C132.2 C133.2 D34.1 D35.2(K) R175.2 R188.1 R189.1 R190.1 R299.1 R303.1 T5.1 U12.8(GND) U12.25(EP) U13.5(GND)
CS2-_1212_input1: C113.1 R155.1 U12.23(CS2-)  [project net CS2-_1212_input1_2]
DRN: C116.2 C124.1 R165.1 R305.2 U12.24(DRN)  [project net DRN_2]
DRN_Q13: Q7.5-6-7-8(D) R153.2 R155.2  [project net DRN_Q13_2]
DRN_U16: Q10.5-6-7-8(D) Q12.5-6-7-8(D) R162.2 R163.2 R165.2 R298.1 RNTC_2.2  [project net DRN_U16_2]
G_TPS1212_input1: R157.1 R158.2 TP13.1 U12.13(G)  [project net G_TPS1212_input1_2]
I2t_TPS1212_input1: C129.2 TP17.1 U12.12(I2t)  [project net I2t_TPS1212_input1_2]
IMON_TPS1212_input1: C132.1 R299.2 TP18.1 U12.9(IMON) U13.3(GPIO2) ; port IMON_TPS1212_input1
IOC_TPS1212_input1: C131.1 R189.2 U12.11(IOC)  [project net IOC_TPS1212_input1_2]
ITMPO_TPS1212_input1: C130.1 R188.2 U12.10(ITMPO) ; port ITMPO_TPS1212_input1
nFAULT_1212_1: D37.1(K) R184.1 R185.1 U12.6(~{FLT})  [project net nFAULT_1212_1_2]
nFLT_TPS1212_input1: R185.2 ; port nFLT_TPS1212_input1
SRC_U16: C125.1 C126.2 Q7.2(S) Q7.3(S) Q7.4(S) Q9.2(S) Q9.3(S) Q9.4(S) Q10.2(S) Q10.3(S) Q10.4(S) Q11.2(S) Q11.3(S) Q11.4(S) Q12.2(S) Q12.3(S) Q12.4(S) R159.1 R160.1 TP51.1 U12.15(SRC)  [project net SRC_U16_2]
TMR_TPS1212_input1: C133.1 R190.2 U12.7(TMR)  [project net TMR_TPS1212_input1_2]
TPLD_LATCH_RST: U13.1(GPI) ; port TPLD_LATCH_RST
TPS1212_1_IDIR: R181.1 ; port IDIR_TPS1212_input1  [project net IDIR_TPS1212_input1]
TPS1212_1_INP: R176.1 U13.4(GPIO4) ; port INP_TPS1212_input1  [project net INP_TPS1212_input1]
TPS1212_1_LPM: Q13.1(G) R178.1 ; port nLPM_TPS1212_input1  [project net nLPM_TPS1212_input1]
VS_ORing: D32.1(K) D33.1(K) R166.2 TP47.1 ; port VS_ORing
WAKE_TPS1212_input1: R187.2 ; port WAKE_TPS1212_input1
WAKE_TPS1212_input1: C127.1 R186.1 R187.1 U12.5(WAKE)  [project net WAKE_TPS1212_input1_2]  [a separate net that carries the same name]
NetC113_2: C113.2 R154.1
NetC114_2: C114.2 R158.1
NetC119_1: C119.1 C120.1 R166.1 R172.2 TP48.1 U12.22(VS)
NetC121_1: C121.1 R168.1 U12.19(CS1-)
NetC121_2: C121.2 R167.1 U12.20(CS1+)
NetC122_1: C122.1 R174.1
NetC123_1: C123.1 Q13.3(D) R172.1 U12.1(EN/UVLO)
NetC124_2: C124.2 R177.1 R305.1 U12.21(ISCP)
NetC126_1: C126.1 TP52.1 U12.14(BST)
NetD35_1: D35.1(A) R161.1
NetD36_1: D36.1(K) R191.2
NetD36_2: D36.2(A) R169.1 R170.1 R171.1 R173.1 R174.2 R182.1 TP16.1
NetD37_2: D37.2(A) R183.1
NetD51_1: D51.1(K) R182.2
NetD51_2: D51.2(A) R191.1 U12.16(GATE)
NetD53_1: D53.1(K) R298.2
NetJ20_1: J20.1 U13.6(GPIO5)
NetJ20_2: J20.2 U13.7(GPIO6)
NetJ20_3: J20.3 U13.8(GPIO7)
NetJ20_4: J20.4 U13.9(GPIO9)
NetQ7_1: Q7.1(G) R157.2
NetQ9_1: Q9.1(G) R171.2
NetQ10_1: Q10.1(G) R169.2
NetQ11_1: Q11.1(G) R170.2
NetQ12_1: Q12.1(G) R173.2
NetQ13_2: Q13.2(S) R175.1
NetR156_1: R156.1 R181.2 U12.4(I_DIR)
NetR163_1: R163.1 R167.2
NetR164_1: R164.1 R168.2
NetR176_2: R176.2 U12.3(INP)
NetR178_2: R178.2 U12.2(~{LPM})
NetR179_1: R179.1 R180.1
NetR179_2: R179.2 U12.18(TMP)
NetR180_2: R180.2 RNTC_2.1
NetR302_1: R302.1 R303.2 U13.2(GPIO1)

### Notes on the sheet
- (near R153) Low Power Path
- TPS1212-Q1_input1
- Capacitive Precharge Settings
- change Diode to handle current
- 500 uohm, 6W rating
  @60A, P_each_res = 1W
- Vclamp = 56.7-62.7V
- FET Vds = 80V. Ids = 43.5A
- 70A Connector
- Connector for off board DC/DC
- (near D33) Main Path
- LED for 48V rail on
- Vref = 3.1V
- Over Current Protection Setting
- I2t Timer Setting
- Circuit Breaker Timer Setting
- ITMPO Output
- Current Monitor Scaling
- 72A
- 1s
- 1.2s with Latch-off
- 3V3 at 150C
- 3V3 at 88A

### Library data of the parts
C113 C121 = CMP-0007081-4: CAP, CERM, 1000 pF, 100 V, +/- 10%, X7R, AEC-Q200 Grade 1, 0603; Manufacturer: TDK; TaMin_C: -55°C; ESR_ohm: 1.9714; Polarized: N; SizeAreaWB_mm2: 4.68; Value1: 1.97137 ohm; U/M: EA; Value: 1000pF; TaMax_C: 125°C; SizeZ_mm: 1; SizeX_mm: 1.6; SizeY_mm: 0.8; SizeArea_mm2: 1.28; AEC Qualified: Y; IRMS_A: 305.705mA; AEC Category: Q200
C114 C116 C122 = CMP-0077895-3: CAP, CERM, 0.22 µF, 100 V,+/- 20%, X7S, AEC-Q200 Grade 1, 0603; Manufacturer: Taiyo Yuden; TaMin_C: -55°C; Polarized: N; SizeAreaWB_mm2: 4.68; U/M: EA; Value: 0.22uF; TaMax_C: 125°C; SizeZ_mm: 1.0; SizeX_mm: 1.6; SizeY_mm: 0.8; SizeArea_mm2: 1.28; AEC Qualified: Y; Cap_F: 220nF; AEC Grade: 1; AEC Category: Q200
C115 C117 = CMP-0009477-2: CAP, CERM, 15 uF, 100 V, +/- 20%, X7R, Stacked 2220; Manufacturer: MuRata; TaMin_C: -55°C; Polarized: N; SizeAreaWB_mm2: 59.13; Value1: Unknown; U/M: EA; Value: 15uF; TaMax_C: 125°C; SizeZ_mm: 6.7; SizeX_mm: 6.1; SizeY_mm: 5.3; Cap_Case: 2220; Value2: 100V; SizeArea_mm2: 32.33; Cap_F: 15µF; AEC Category: Q200
C118 C119 C124 = CMP-0081011-1: as C64 on sheet Power
C120 C123 = CMP-0007082-4: CAP, CERM, 0.01 uF, 100 V, +/- 10%, X7R, AEC-Q200 Grade 1, 0603; Manufacturer: TDK; TaMin_C: -55°C; ESR_ohm: 0.2354; Polarized: N; SizeAreaWB_mm2: 4.68; Value1: 0.235428 ohm; U/M: EA; Value: 0.01uF; TaMax_C: 125°C; SizeZ_mm: 1; SizeX_mm: 1.6; SizeY_mm: 0.8; SizeArea_mm2: 1.28; AEC Qualified: Y; IRMS_A: 396.995mA; AEC Category: Q200
C125 = CMP-0007969-2: CAP, CERM, 0.1 uF, 100 V, +/- 10%, X7R, AEC-Q200 Grade 1, 0805; Manufacturer: TDK; TaMin_C: -55°C; ESR_ohm: 0.020726; Polarized: N; SizeAreaWB_mm2: 6.75; Value1: 0.020726 ohm; U/M: EA; Value: 0.1uF; TaMax_C: 125°C; SizeZ_mm: 1.45; SizeX_mm: 2; SizeY_mm: 1.25; Cap_Case: 0805; SizeArea_mm2: 2.5; AEC Qualified: Y; IRMS_A: 1.456A; AEC Grade: 1; AEC Category: Q200
C126 = CMP-0122257-1: 1 µF ±10% 50V Ceramic Capacitor X7R 0603 (1608 Metric); Manufacturer: Samsung; AEC Grade: Grade 1; AEC Qualified: Yes; SizeZ_mm: 1mm; TempCo: 15%; ValueDisplayed: 1uF; Value: 1µF
C127 = CMP-0006687-2: CAP, CERM, 330 pF, 50 V, +/- 10%, X7R, 0402; Manufacturer: MuRata; TaMin_C: -55°C; Polarized: N; SizeAreaWB_mm2: 3; Value1: Unknown; U/M: EA; Value: 330pF; TaMax_C: 125°C; SizeZ_mm: 0.6; SizeX_mm: 1; SizeY_mm: 0.5; AEC Category: Q200
C128 = CMP-0007135-2: as C199 on sheet (SPI Expander) TXE8124-Q1
C129 = CMP-0095670-2: as C59 on sheet Power
C130 C132 = CMP-0006921-4: CAP, CERM, 330 pF, 50 V, +/- 10%, X7R, 0603; Manufacturer: Kemet; TaMin_C: -55°C; Polarized: N; SizeAreaWB_mm2: 4.68; Value1: Unknown; U/M: EA; Value: 330pF; TaMax_C: 125°C; SizeZ_mm: 1; SizeX_mm: 1.6; SizeY_mm: 0.8; SizeArea_mm2: 1.28; AEC Category: Q200
C131 C133 = CMP-0007079-4: CAP, CERM, 0.047 uF, 50 V, +/- 10%, X7R, AEC-Q200 Grade 1, 0603; Manufacturer: TDK; TaMin_C: -55°C; ESR_ohm: 49.007m; Polarized: N; SizeAreaWB_mm2: 4.68; Value1: 0.049007 ohm; U/M: EA; TaMax_C: 125°C; SizeZ_mm: 1; SizeX_mm: 1.6; SizeY_mm: 0.8; SizeArea_mm2: 1.28; AEC Qualified: Y; IRMS_A: 767.528mA; AEC Category: Q200
D32 D33 = CMP-0029014-2: Diode, Ultrafast, 400 V, 1 A, 1408 Diode; Manufacturer: Bourns; SizeAreaWB_mm2: 12.76; SizeZ_mm: 1.15; Value2: 1.05V; Green_REACh: Incomplete; SizeY_mm: 1.9; Value: 400V; TJmax_C: 150°C; Io_A: 1A; AEC Category: Q101; RJC_CperW: 40; SizeX_mm: 3.4; SizeArea_mm2: 6.46; Green_Lifecycle: Not Set
D34 = CMP-0085022-1: Diode, TVS, Bi, 51 V, 82.4 Vc, 400 W, 4.9 A, SMA (non-polarized); Manufacturer: Littelfuse; AEC Qualified: N; SizeZ_mm: 2.65; AEC Category: Q101; RJA_CperW: 120; SizeX_mm: 5.075; Vc: 82.4V; SizeY_mm: 2.575; Vbr_Max: 62.7V; Vbr_Min: 56.7V; Ppk: 400W; Ipp: 4.9A; SizeAreaWB_mm2: 32.368125; SizeArea_mm2: 13.068125
D35 = CMP-0078478-1: as D11 on sheet Power
D36 D51 D53 = CMP-0076974-1: Diode, Switching, 100 V, 0.15 A, SOD-123; Manufacturer: Micro Commercial Components; SizeAreaWB_mm2: 13.095; Vr_V: 100V; SizeArea_mm2: 6.545; TJmax_C: 150°C; AEC Category: Q101; Value: 100V; SizeZ_mm: 1.35; Green_REACh: Incomplete; Io_A: 150mA; Vf_V: 1.25V; SizeY_mm: 1.7; Green_Lifecycle: Not Set; U/M: EA; Value1: 0.15A; SizeX_mm: 3.85
D37 = CMP-0002893-1: LED, Super Red, SMD; Manufacturer: Wurth Elektronik; Io_A: 20mA; Value1: W; U/M: EA; Vf_V: 1.9V; Type: AlInGaP
J20 = CMP-0075409-2: Header, 100mil, 4x1, Gold, TH; Manufacturer: Samtec; Pitch_mm: 2.54; Cert_VDE: N; Gender: Male; Cert_CSA: Y; Voltage_V: 550V; Green_REACh: Passed; Current_A: 6.3A; Green_Lifecycle: Active; Row_Count: 1
Q7 Q9-Q12 = CMP-0088066-1: N-Channel Power MOSFET 80V 3374A 1.1mOhm 8-Pin DFNW Surface Mount T/R; Manufacturer: ON Semiconductor; IdsMax_A: 43.5A; Vgs_V: 20V; AEC Qualified: Yes; ChMode: False; QgTyp_nC: 147nC @ 10V; SizeZ_mm: 1.2mm; Rdson45_ohm: 930µ
Q13 = CMP-0000757-1: MOSFET, N-CH, 50 V, 0.2 A, SOT-323; Alternate Manufacturer: None; Manufacturer: Diodes Inc.; SizeZ_mm: 1.1; ChType: N; Value1: 3; VdsMax_V: 50V; SizeX_mm: 2.2; Vgs_V: 1.5V; Value: 50V; Rdson45_ohm: 3.5; SizeArea_mm2: 4.84; AEC Category: Q101; IdsMax_A: 200mA; SizeAreaWB_mm2: 10.24; U/M: EA
R153 = CMP-0098465-1: 1 Ohms ±1% 3W Chip Resistor 2010 (5025 Metric) Automotive AEC-Q200, Current Sense, Moisture Resistant, Pulse Withstanding; Manufacturer: Isabellenhuette; AEC Grade: Grade 0; AEC Qualified: Yes; SizeZ_mm: 0.55mm; TempCo: 20ppm/°C
R154 R155 R157 R163-R165 R179 R182 R305 = CMP-0025697-4: RES, 0, 5%, 0.1 W, AEC-Q200 Grade 0, 0603; Manufacturer: Vishay-Dale; Power_W: 100mW; TempCo: 200 ppm/C; Value_Code: 0000; Value: 0; EIA_Code: E24; SizeX_mm: 1.6; SizeY_mm: 0.8; SizeZ_mm: 1; Value2: 0.1W; SizeArea_mm2: 1.28; CompType: Resistor; AEC Qualified: Y; VDC_V: 75V; AEC Category: Q200
R156 = CMP-0023078-5: RES, 3.16 k, 1%, 0.1 W, 0603; Manufacturer: Yageo; Power_W: 100mW; TempCo: 100 ppm/C; Value_Code: 3k16; Value: 3.16k; EIA_Code: E96; SizeX_mm: 1.6; SizeY_mm: 0.8; SizeZ_mm: 1; Value2: 0.1W; SizeArea_mm2: 1.28; AEC Qualified: N; VDC_V: 75V; AEC Category: Q200; SizeAreaWB_mm2: 4.68
R158 R174 = CMP-0021863-2: RES, 10.0, 1%, 0.125 W, 0805; Manufacturer: Yageo America; Power_W: 125mW; TempCo: 200 ppm/C; Value_Code: 10R0; U/M: EA; Value: 10.0; EIA_Code: E96; Res_ohm: 10; SizeX_mm: 2; SizeY_mm: 1.25; SizeZ_mm: 1.45; Value2: 0.125W; SizeArea_mm2: 2.5; VDC_V: 150V; AEC Category: Q200
R159 R160 = CMP-0095938-1: 500 µOhms ±1% 6W Chip Resistor 2512 (6432 Metric) Automotive AEC-Q200, Current Sense Metal Element; Manufacturer: Bourns; AEC Qualified: Yes; Standoff Height: 0.15mm; SizeZ_mm: 1.23mm; Value: 500µ; TempCo: 100ppm/°C; AEC Grade: Grade 0
R161 = CMP-0022990-5: RES, 2.49 k, 1%, 0.1 W, 0603; Manufacturer: Yageo; Power_W: 100mW; TempCo: 100 ppm/C; Value_Code: 2k49; Value: 2.49k; EIA_Code: E96; SizeX_mm: 1.6; SizeY_mm: 0.8; SizeZ_mm: 1; Value2: 0.1W; SizeArea_mm2: 1.28; AEC Qualified: N; VDC_V: 75V; AEC Category: Q200; SizeAreaWB_mm2: 4.68
R162 = CMP-0124268-3: 0.25 mOhms ±1% 3W Chip Resistor 2512 (6332 Metric) Automotive AEC-Q200, Current Sense Metal Element; Manufacturer: Shenzhen Milliohm Electronic; AEC Grade: Grade 0; AEC Qualified: Yes; SizeZ_mm: 1.9mm; TempCo: 50ppm/°C
R166 = CMP-0022679-3: RES, 100, 1%, 0.1 W, AEC-Q200 Grade 0, 0603; Manufacturer: Panasonic; Power_W: 100mW; TempCo: 100 ppm/C; Value_Code: 100R; U/M: EA; Value: 100; EIA_Code: E96; SizeX_mm: 1.6; SizeY_mm: 0.8; SizeZ_mm: 1; Value2: 0.1W; SizeArea_mm2: 1.28; AEC Qualified: Y; AEC Grade: 0; AEC Category: Q200
R167 R168 = CMP-0022902-5: as R58 on sheet Power
R169-R171 R173 = CMP-0023007-4: RES, 2.21, 1%, 0.1 W, 0603; Manufacturer: Yageo; Power_W: 100mW; TempCo: 200 ppm/C; Value_Code: 2R21; Value: 2.21; EIA_Code: E96; SizeX_mm: 1.6; SizeY_mm: 0.8; SizeZ_mm: 1; Value2: 0.1W; SizeArea_mm2: 1.28; AEC Qualified: N; VDC_V: 75V; AEC Category: Q200; SizeAreaWB_mm2: 4.68
R172 = CMP-0023012-4: RES, 300 k, 1%, 0.1 W, 0603; Manufacturer: Yageo; Power_W: 100mW; TempCo: 100 ppm/C; Value: 300k; SizeX_mm: 1.6; SizeY_mm: 0.8; SizeZ_mm: 1; Value2: 0.1W; SizeArea_mm2: 1.28; AEC Qualified: N; VDC_V: 75V; AEC Category: Q200; SizeAreaWB_mm2: 4.68
R175 = CMP-0023267-5: RES, 75.0 k, 1%, 0.1 W, 0603; Manufacturer: Yageo; Power_W: 100mW; TempCo: 100 ppm/C; Value_Code: 75k0; Value: 75.0k; EIA_Code: E96; Res_ohm: 75k; SizeX_mm: 1.6; SizeY_mm: 0.8; SizeZ_mm: 1; Value2: 0.1W; SizeArea_mm2: 1.28; AEC Qualified: N; VDC_V: 75V; AEC Category: Q200; SizeAreaWB_mm2: 4.68
R176 R178 R181 R185 R187 R302 = CMP-0022895-5: RES, 1.00 k, 1%, 0.1 W, 0603; Manufacturer: Yageo; Power_W: 100mW; TempCo: 100 ppm/C; Value_Code: 1k00; Value: 1.00k; EIA_Code: E96; Res_ohm: 1k; SizeX_mm: 1.6; SizeY_mm: 0.8; SizeZ_mm: 1; Value2: 0.1W; SizeArea_mm2: 1.28; AEC Qualified: N; VDC_V: 75V; AEC Category: Q200; SizeAreaWB_mm2: 4.68
R177 = CMP-0023243-5: RES, 698, 1%, 0.1 W, 0603; Manufacturer: Yageo; Power_W: 100mW; TempCo: 100 ppm/C; Value_Code: 698R; Value: 698; EIA_Code: E96; SizeX_mm: 1.6; SizeY_mm: 0.8; SizeZ_mm: 1; Value2: 0.1W; SizeArea_mm2: 1.28; AEC Qualified: N; VDC_V: 75V; AEC Category: Q200; SizeAreaWB_mm2: 4.68
R180 = CMP-0023017-5: RES, 309, 1%, 0.1 W, 0603; Manufacturer: Yageo; Power_W: 100mW; TempCo: 100 ppm/C; Value_Code: 309R; Value: 309; EIA_Code: E96; SizeX_mm: 1.6; SizeY_mm: 0.8; SizeZ_mm: 1; Value2: 0.1W; SizeArea_mm2: 1.28; AEC Qualified: N; VDC_V: 75V; AEC Category: Q200; SizeAreaWB_mm2: 4.68
R183 = CMP-0022904-5: RES, 205, 1%, 0.1 W, 0603; Manufacturer: Yageo; Power_W: 100mW; TempCo: 100 ppm/C; Value_Code: 205R; Value: 205; EIA_Code: E96; SizeX_mm: 1.6; SizeY_mm: 0.8; SizeZ_mm: 1; Value2: 0.1W; SizeArea_mm2: 1.28; AEC Qualified: N; VDC_V: 75V; AEC Category: Q200; SizeAreaWB_mm2: 4.68
R184 R186 = CMP-0025686-1: RES, 10.0 k, 0.1%, 0.1 W, AEC-Q200 Grade 1, 0603; Manufacturer: Vishay-Dale; Power_W: 100mW; TempCo: 25 ppm/C; Value_Code: 10k0; U/M: EA; Value: 10.0k; EIA_Code: E192; Res_ohm: 10k; SizeX_mm: 1.6; SizeY_mm: 0.85; SizeZ_mm: 0.55; Value2: 0.1W; SizeArea_mm2: 1.36; AEC Qualified: Y; VDC_V: 75V; AEC Grade: 1; AEC Category: Q200
R188 = CMP-0022986-5: RES, 2.20 k, 1%, 0.1 W, 0603; Manufacturer: Yageo; Power_W: 100mW; TempCo: 100 ppm/C; Value_Code: 2k20; Value: 2.20k; Res_ohm: 2.2k; SizeX_mm: 1.6; SizeY_mm: 0.8; SizeZ_mm: 1; Value2: 0.1W; SizeArea_mm2: 1.28; AEC Qualified: N; VDC_V: 75V; AEC Category: Q200; SizeAreaWB_mm2: 4.68
R189 = CMP-0022776-5: RES, 12.1 k, 1%, 0.1 W, 0603; Manufacturer: Yageo; Power_W: 100mW; TempCo: 100 ppm/C; Value_Code: 12k1; Value: 12.1k; EIA_Code: E96; SizeX_mm: 1.6; SizeY_mm: 0.8; SizeZ_mm: 1; Value2: 0.1W; SizeArea_mm2: 1.28; AEC Qualified: N; VDC_V: 75V; AEC Category: Q200; SizeAreaWB_mm2: 4.68
R190 = CMP-0021990-4: RES, 100 k, 1%, 0.1 W, AEC-Q200 Grade 0, 0603; Manufacturer: Vishay-Dale; Power_W: 100mW; TempCo: 100 ppm/C; Value: 100k; EIA_Code: E96; SizeX_mm: 1.6; SizeY_mm: 0.8; SizeZ_mm: 1; Value2: 0.1W; SizeArea_mm2: 1.28; AEC Qualified: Y; VDC_V: 75V; AEC Category: Q200; AEC Grade: 0
R191 = CMP-0022751-4: RES, 10.0, 1%, 0.1 W, 0603; Manufacturer: Yageo; Power_W: 100mW; TempCo: 100 ppm/C; Value_Code: 10R0; Value: 10.0; EIA_Code: E96; Res_ohm: 10; SizeX_mm: 1.6; SizeY_mm: 0.8; SizeZ_mm: 1; Value2: 0.1W; SizeArea_mm2: 1.28; AEC Qualified: N; VDC_V: 75V; AEC Category: Q200; SizeAreaWB_mm2: 4.68
R298 = CMP-0022738-5: RES, 102, 1%, 0.1 W, 0603; Manufacturer: Yageo; Power_W: 100mW; TempCo: 100 ppm/C; Value_Code: 102R; Value: 102; EIA_Code: E96; SizeX_mm: 1.6; SizeY_mm: 0.8; SizeZ_mm: 1; Value2: 0.1W; SizeArea_mm2: 1.28; AEC Qualified: N; VDC_V: 75V; AEC Category: Q200; SizeAreaWB_mm2: 4.68
R299 = CMP-0023037-5: RES, 33.0 k, 1%, 0.1 W, 0603; Manufacturer: Yageo; Power_W: 100mW; TempCo: 100 ppm/C; Value_Code: 33k0; Value: 33.0k; Res_ohm: 33k; SizeX_mm: 1.6; SizeY_mm: 0.8; SizeZ_mm: 1; Value2: 0.1W; SizeArea_mm2: 1.28; AEC Qualified: N; VDC_V: 75V; AEC Category: Q200; SizeAreaWB_mm2: 4.68
R303 = CMP-0022814-5: RES, 15.4 k, 1%, 0.1 W, 0603; Manufacturer: Yageo; Power_W: 100mW; TempCo: 100 ppm/C; Value_Code: 15k4; Value: 15.4k; EIA_Code: E96; SizeX_mm: 1.6; SizeY_mm: 0.8; SizeZ_mm: 1; Value2: 0.1W; SizeArea_mm2: 1.28; AEC Qualified: N; VDC_V: 75V; AEC Category: Q200; SizeAreaWB_mm2: 4.68
RNTC_2 = CMP-0095715-1: NTC Thermistor for Temperature Sensor, Automotive, 0603, 47kΩ, 5%, 0.046mA, 5V; Manufacturer: Murata; B 25 50: 4050K; B 25 100: 4131K; SizeZ_mm: 0.95mm; AEC Qualified: Yes; B 25 85: 4108K; B Tolerance: 1%; Automotive Grade: Grade 0
T3-T5 = CMP-0075010-2: Terminal 70A Lug; PartNumber: CXS70-14-C; Manufacturer: Panduit; CompType: Screw Terminal; CT: False; Green_Lifecycle: Not Set; Green_REACh: Incomplete
TP13 TP16-TP18 TP51 TP52 = CMP-0055149-1: Test Point, Multipurpose, White, TH; Manufacturer: Keystone; CNHeader: FALSE; Green_Lifecycle: Active; Green_REACh: Passed; ContactFinish: Silver; CT: TRUE
TP14 TP15 = CMP-0055147-2: as TP8 on sheet Power
TP47 TP48 = CMP-0055139-1: Test Point, Miniature, White, TH; Manufacturer: Keystone; CNHeader: FALSE; Green_Lifecycle: Active; Green_REACh: Passed; ContactFinish: Silver; CT: TRUE
U12 = CMP-0124371-1: Low IQ Automotive High Side Switch Controller with Bi-directional IMON, Low Power Mode, Load Wakeup, I2t and Diagnostics; Manufacturer: Texas Instruments; SizeZ_mm: 1mm; AEC Qualified: No; AEC Grade: Grade 1; Max Supply Voltage: 73V; Min Supply Voltage: 3.5V; Number Of Outputs: 1; Standoff Height: 0mm; TJmax_C: +150°C
U13 = CMP-0123509-1: Manufacturer: Texas Instruments; SizeZ_mm: 1.1mm; Standoff Height: 0.05mm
